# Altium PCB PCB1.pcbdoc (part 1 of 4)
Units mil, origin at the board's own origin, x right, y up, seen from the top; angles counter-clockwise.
Board outline 2559.1 x 3937 mil, 4 copper layers (Top Layer, Inner1, Inner2, Bottom Layer), stack 102.8 mil thick; 377 components, 358 nets, 1639 pads, 361 vias.
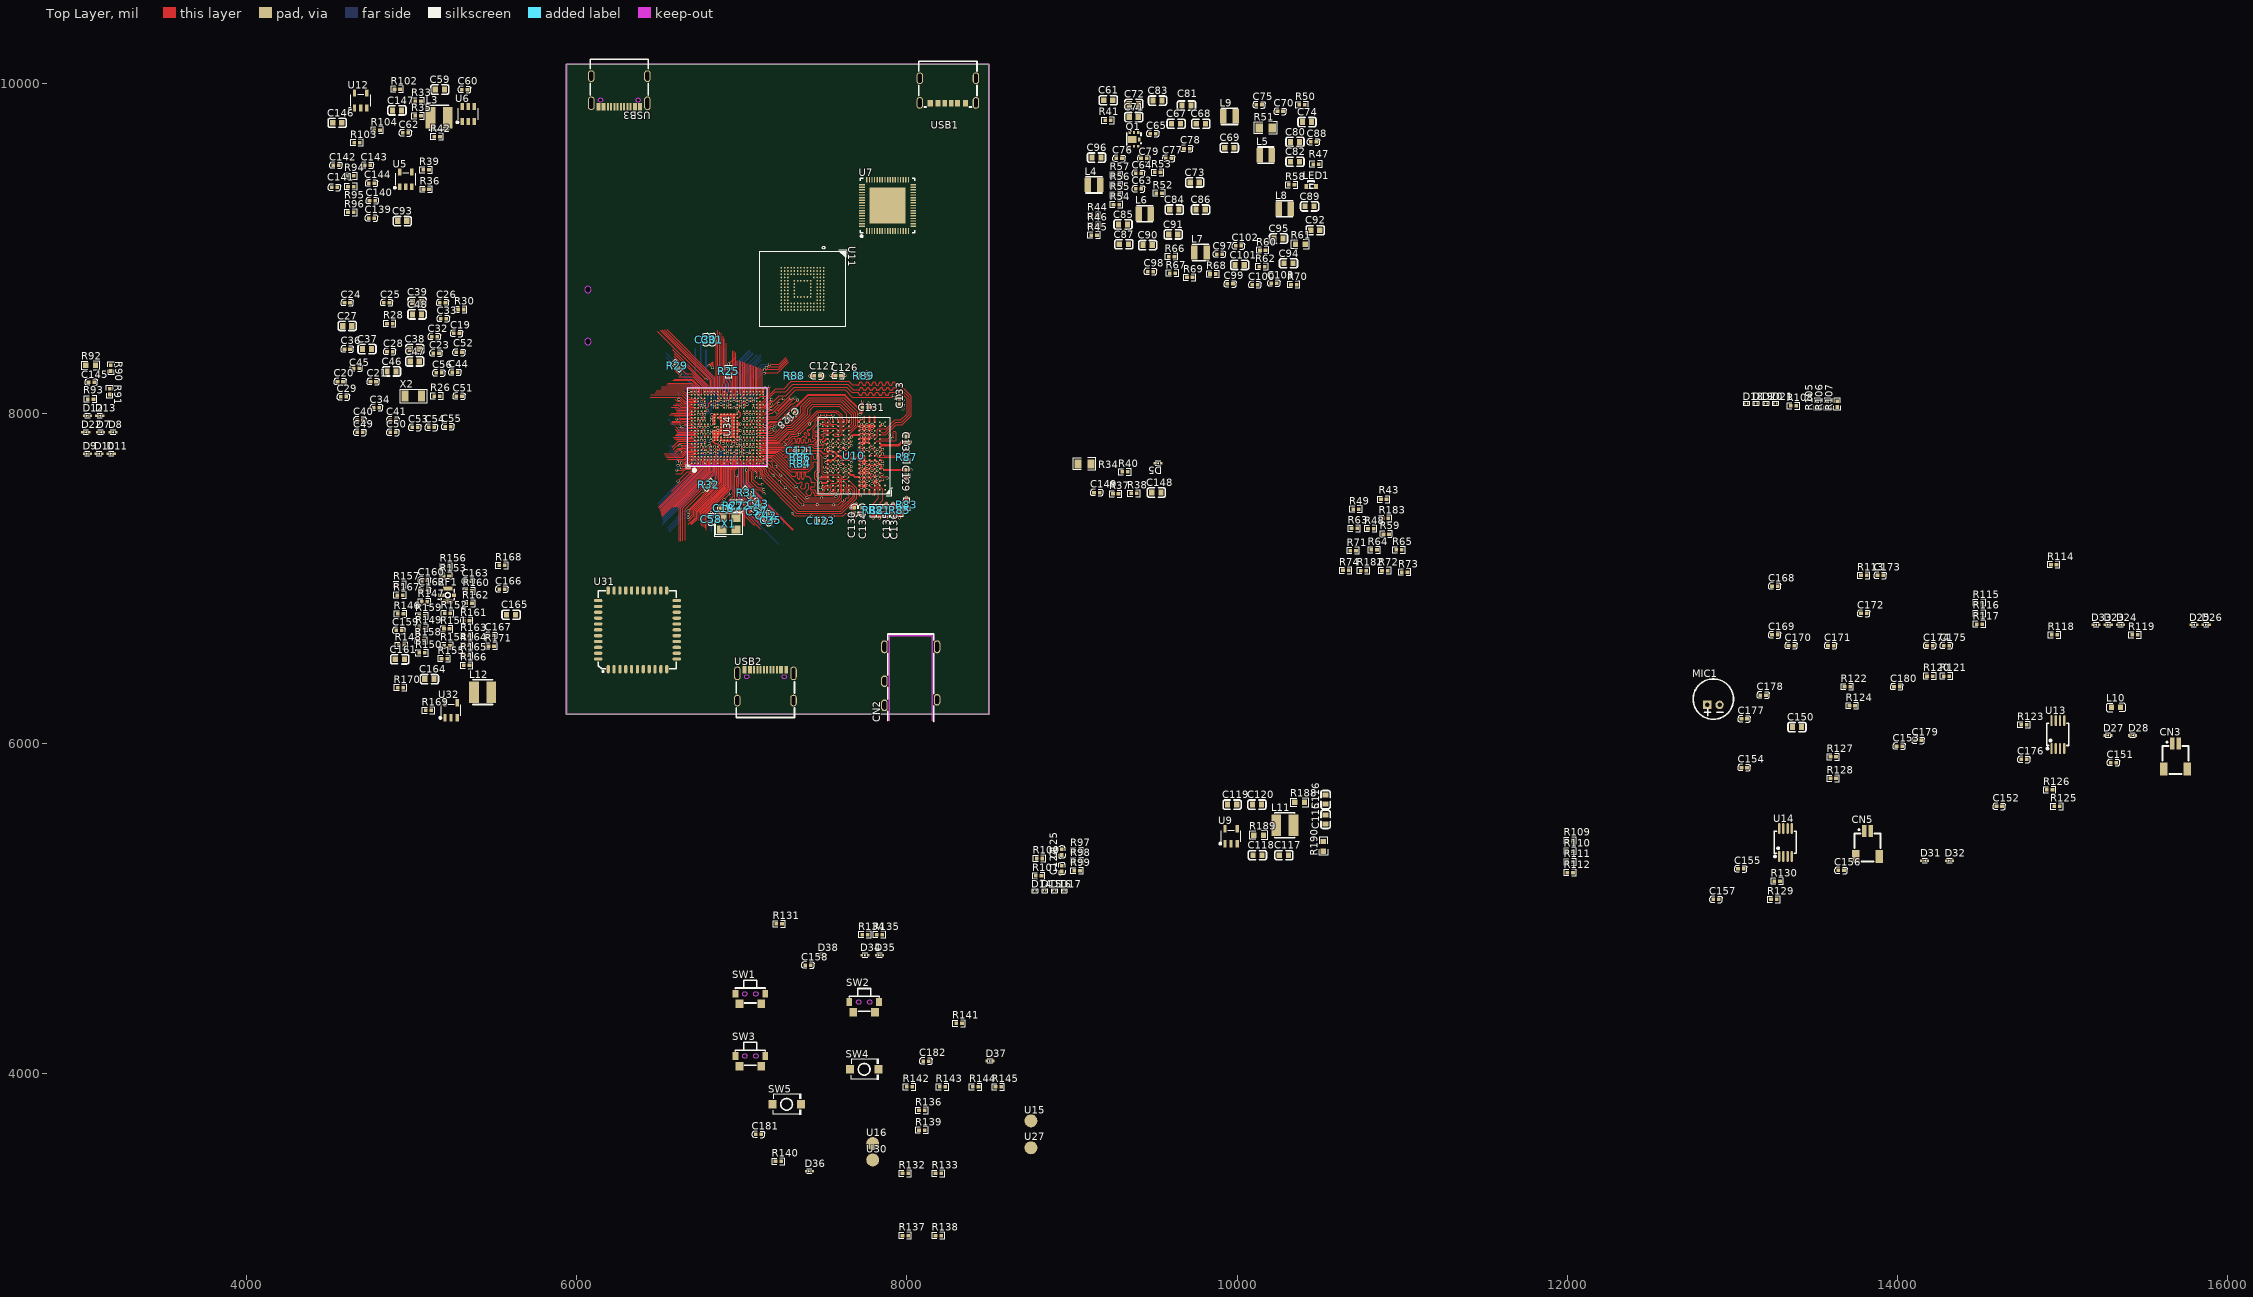
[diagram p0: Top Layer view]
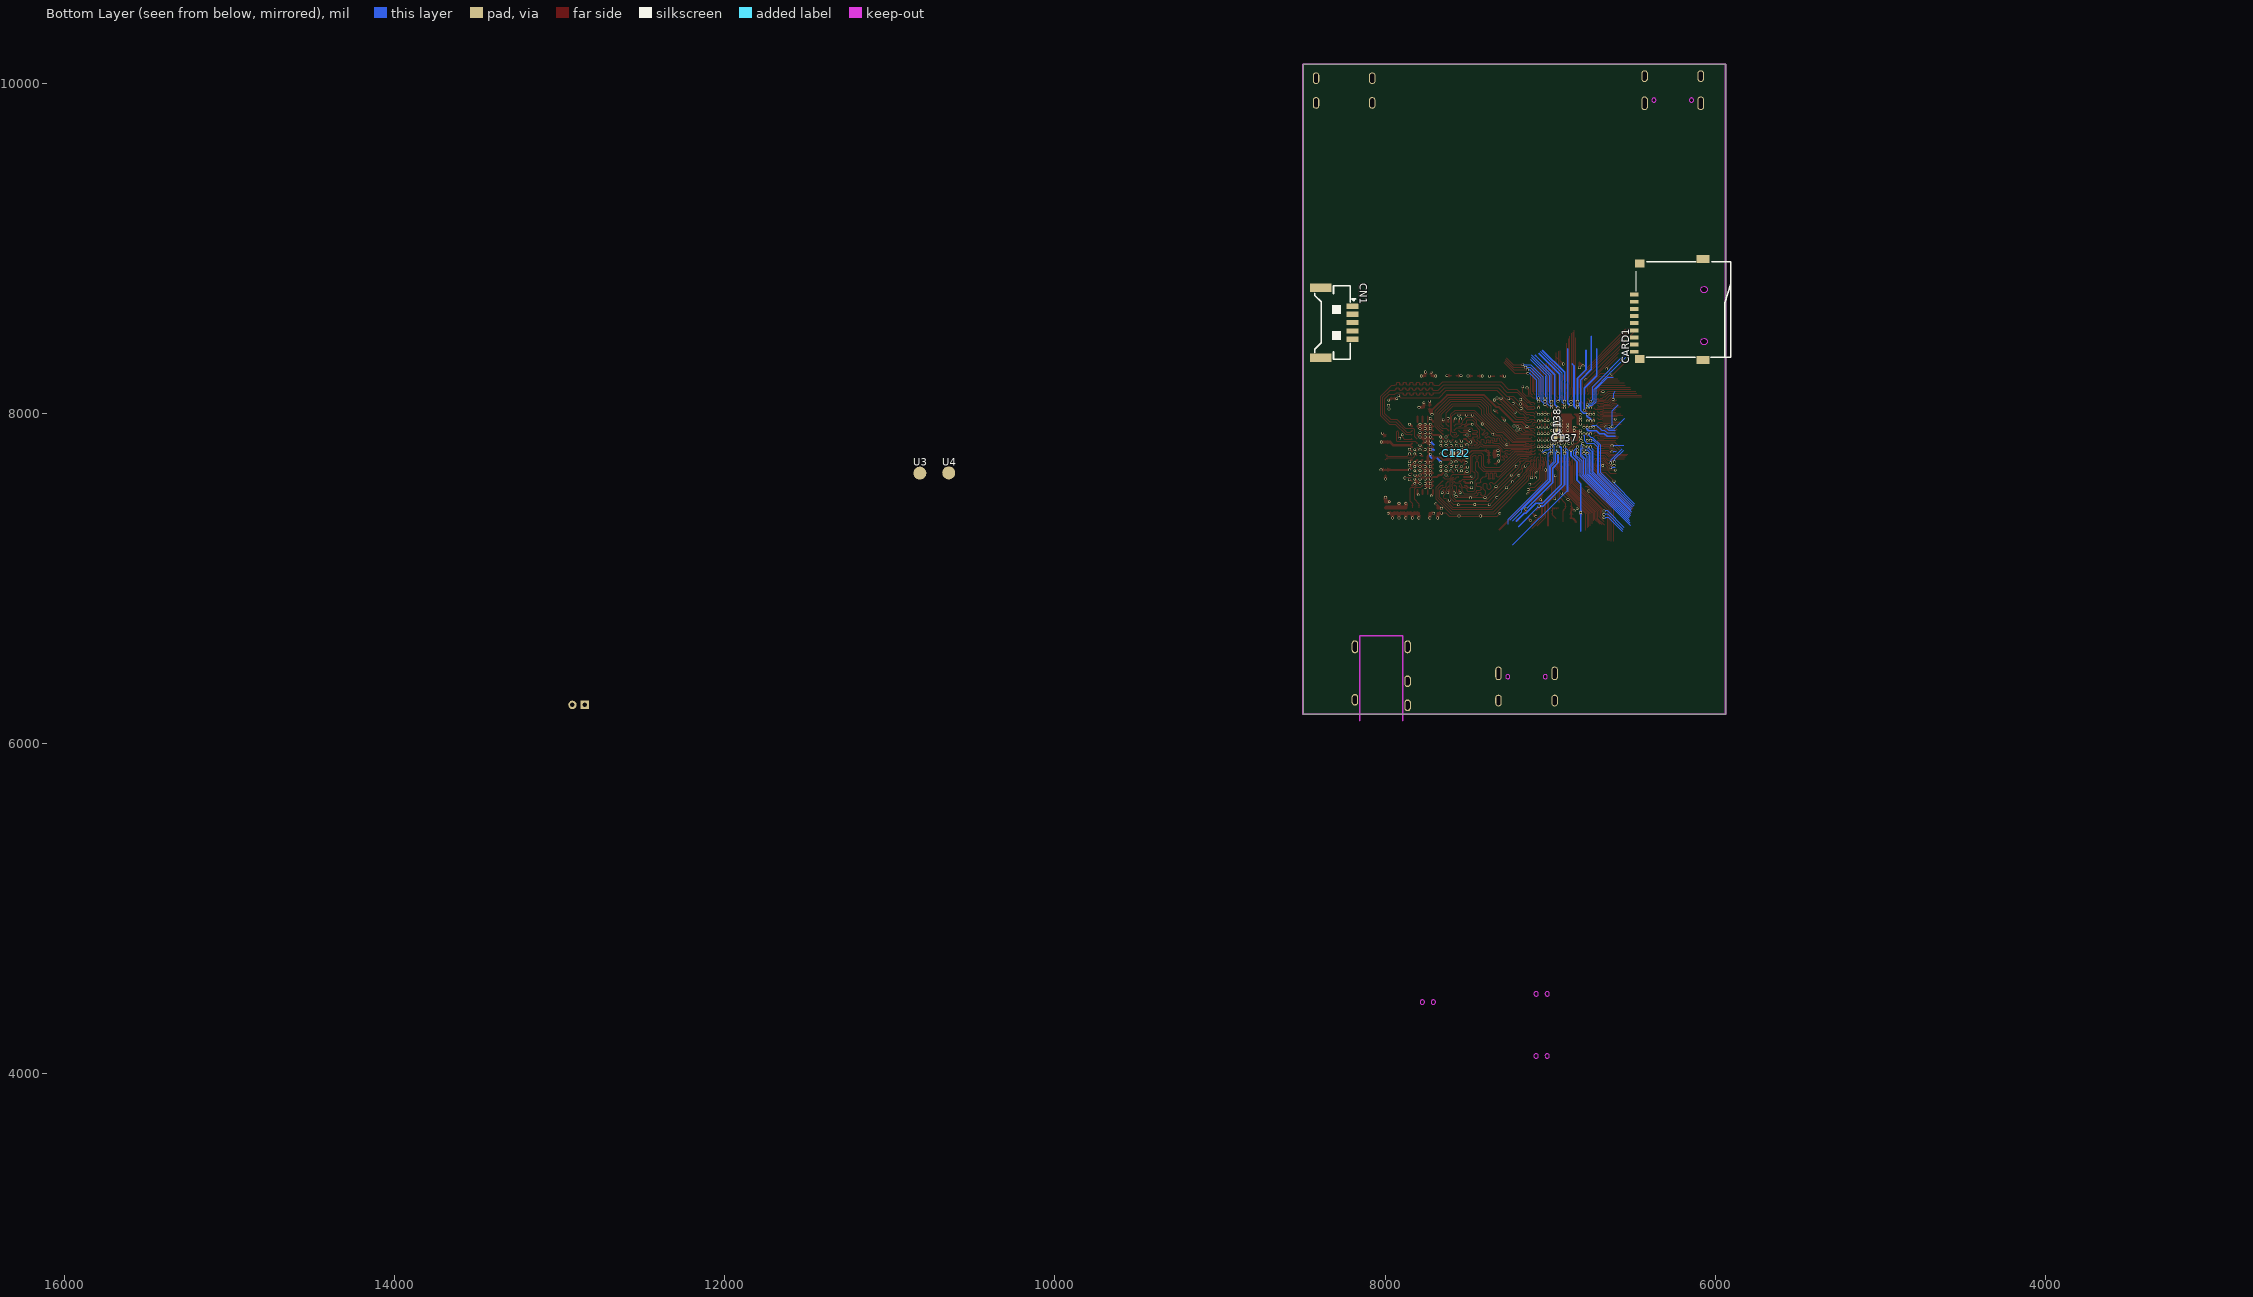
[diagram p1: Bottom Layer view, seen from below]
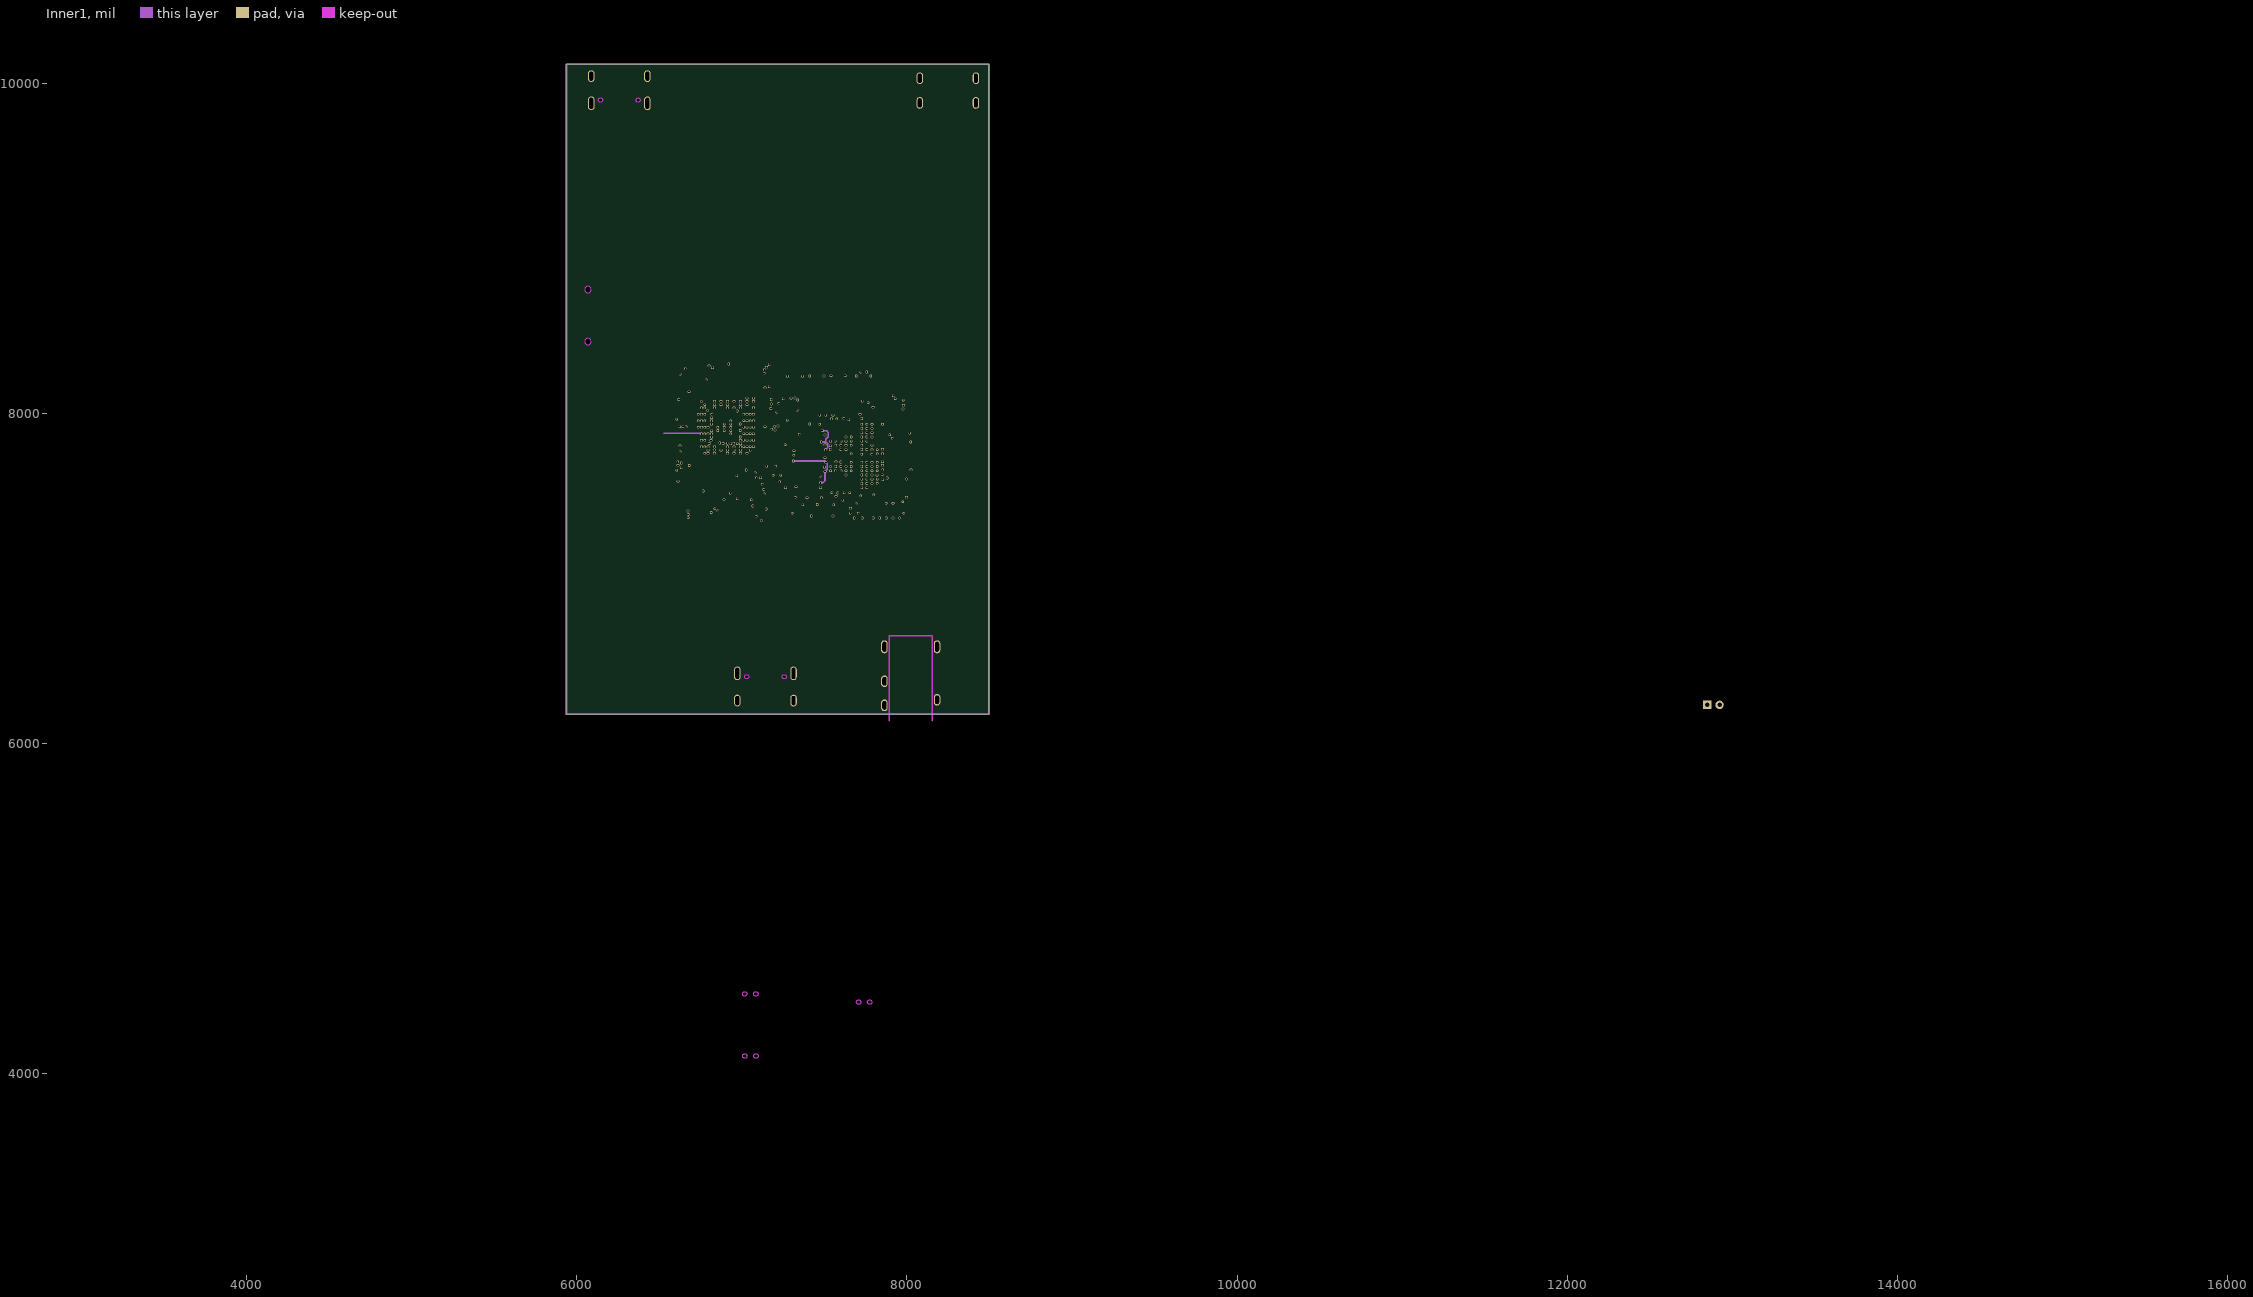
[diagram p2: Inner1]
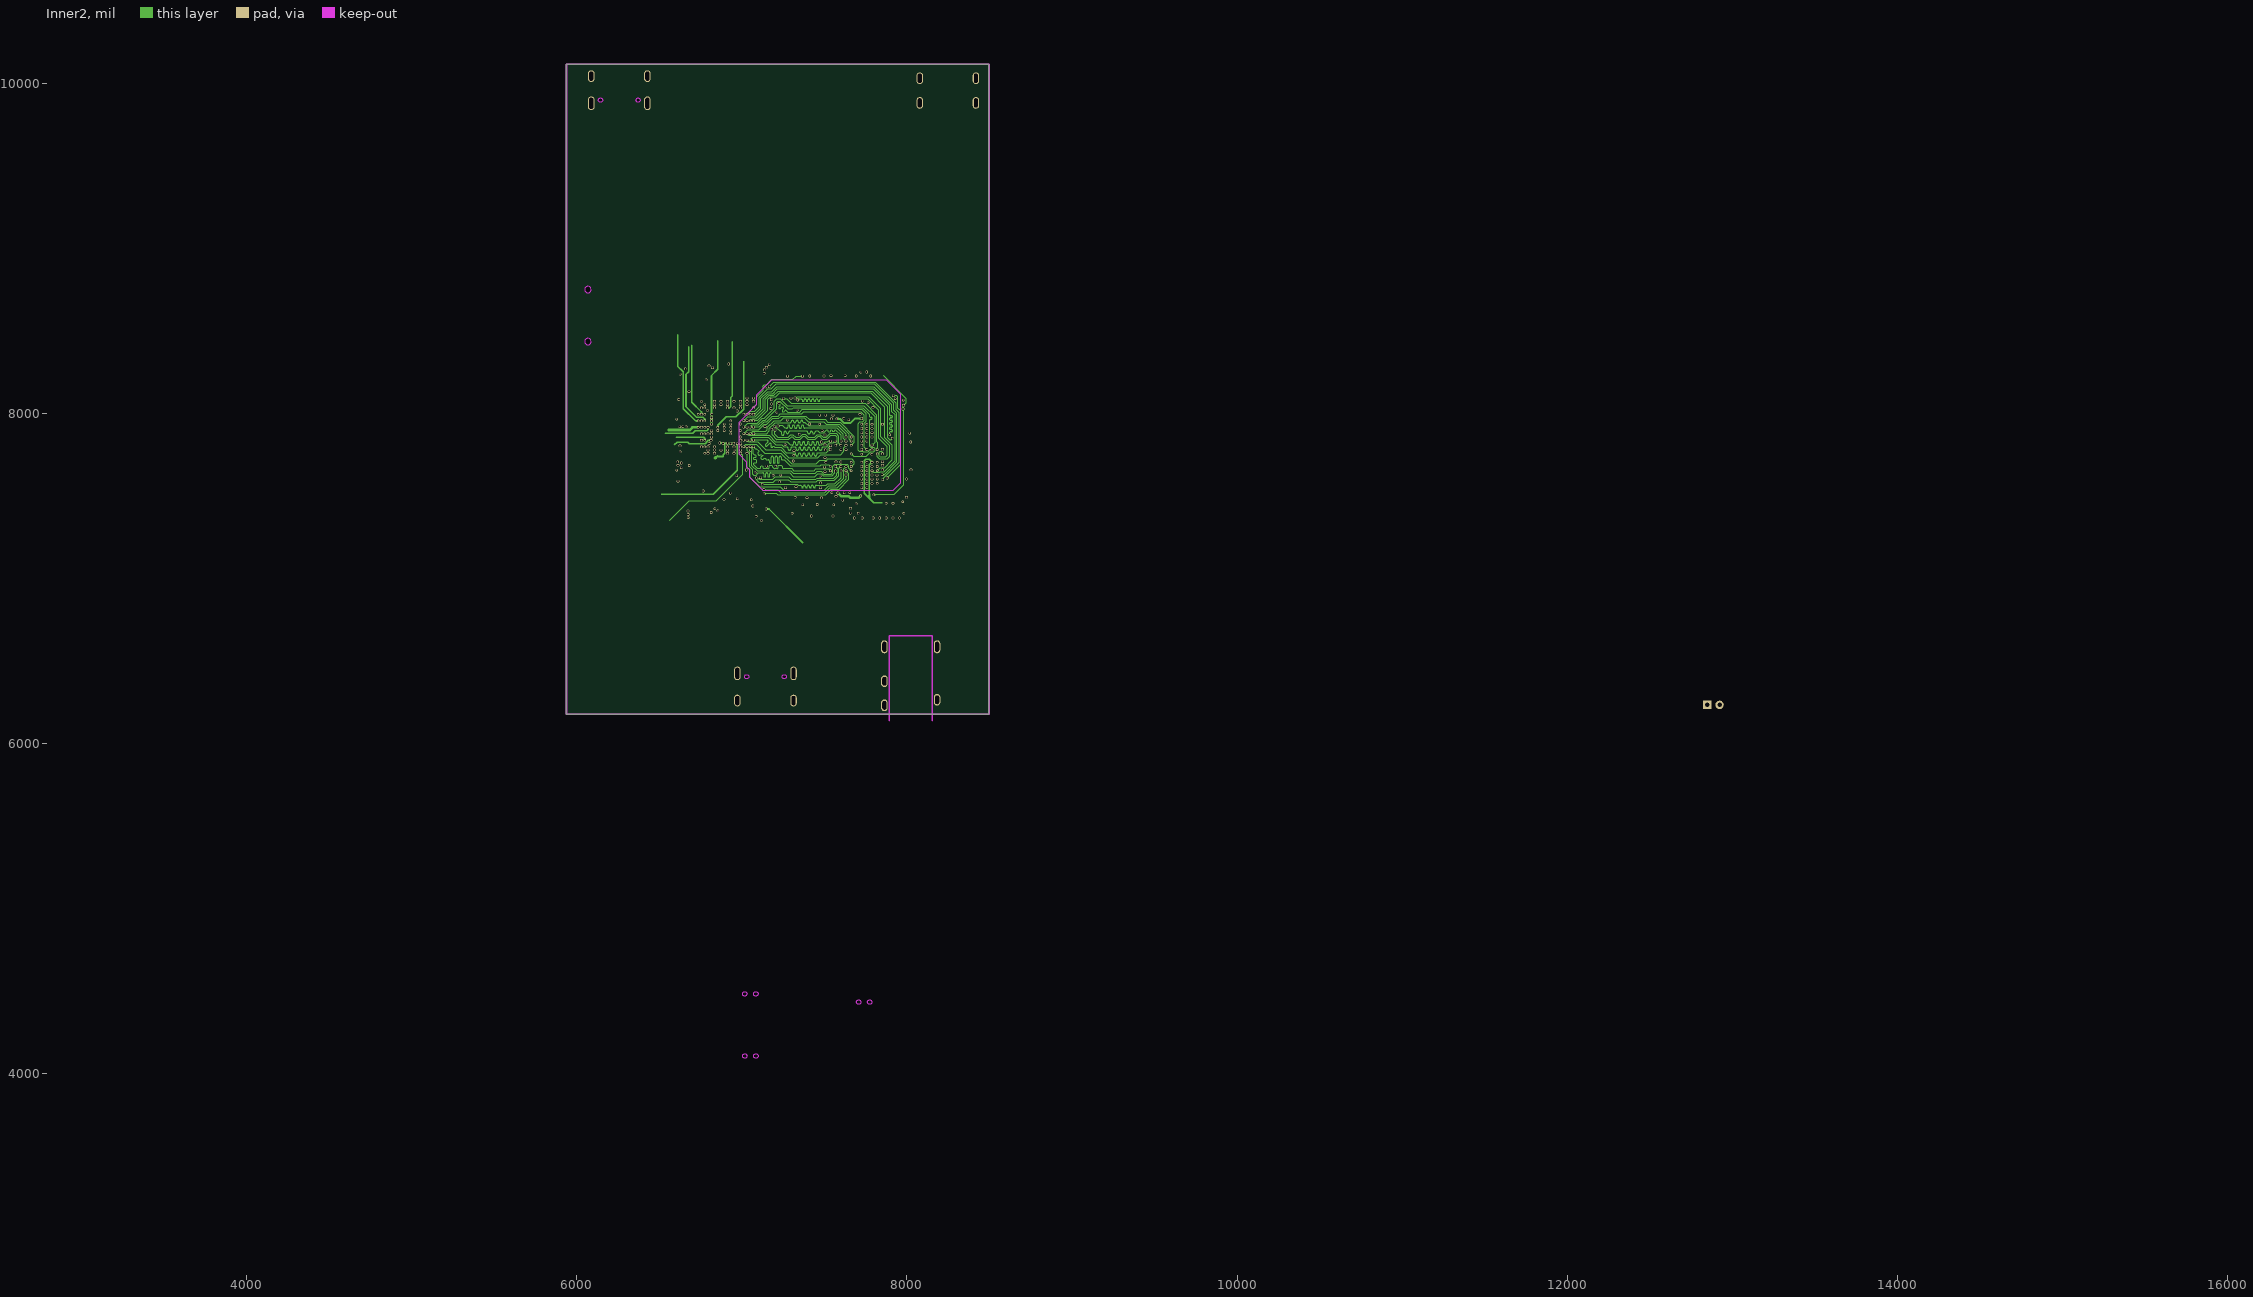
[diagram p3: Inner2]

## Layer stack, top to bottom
Top Solder Mask Layer: solder mask 0.4, Dk 3.3
Top Layer: signal copper 1.4
Dielectric1: surface 59.4, FR4, Dk 4.5
Inner1: signal copper 1.4
Dielectric2: surface 18.9, PP, Dk 4.5
Inner2: signal copper 1.4
Dielectric3: surface 18.9, PP, Dk 4.5
Bottom Layer: signal copper 1.4
Bottom Solder Mask Layer: solder mask 0.4, Dk 3.3

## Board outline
5938.8,10113.3 5938.8,6176.3 8497.9,6176.3 8497.9,10113.3

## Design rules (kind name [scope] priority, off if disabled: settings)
BoardOutlineClearance copperThickness1oz [All] p0: genericclearance=10 ignorepadtopadclearanceinfootprint=FALSE except(0: Arc-SplitContinuation Track-SplitContinuation SMDPad-SplitContinuation THPad-SplitContinuation Via-SplitContinuation Fill-SplitContinuation Poly-SplitContinuation Region-SplitContinuation Text-SplitContinuation)
BoardOutlineClearance copperThickness2oz [All] p0: genericclearance=10 ignorepadtopadclearanceinfootprint=FALSE except(0: Arc-SplitContinuation Track-SplitContinuation SMDPad-SplitContinuation THPad-SplitContinuation Via-SplitContinuation Fill-SplitContinuation Poly-SplitContinuation Region-SplitContinuation Text-SplitContinuation)
BoardOutlineClearance Plane_innerPlane [All] p0: genericclearance=10 ignorepadtopadclearanceinfootprint=FALSE except(0: Arc-SplitContinuation Track-SplitContinuation SMDPad-SplitContinuation THPad-SplitContinuation Via-SplitContinuation Fill-SplitContinuation Poly-SplitContinuation Region-SplitContinuation Text-SplitContinuation)
BoardOutlineClearance Copper_copperRegion [All] p0: genericclearance=10 ignorepadtopadclearanceinfootprint=FALSE except(0: Arc-SplitContinuation Track-SplitContinuation SMDPad-SplitContinuation THPad-SplitContinuation Via-SplitContinuation Fill-SplitContinuation Poly-SplitContinuation Region-SplitContinuation Text-SplitContinuation)
BoardOutlineClearance otherClearance [All] p0: genericclearance=10 ignorepadtopadclearanceinfootprint=FALSE except(0: Arc-SplitContinuation Track-SplitContinuation SMDPad-SplitContinuation THPad-SplitContinuation Via-SplitContinuation Fill-SplitContinuation Poly-SplitContinuation Region-SplitContinuation Text-SplitContinuation)
Clearance copperThickness1oz [All] p1: gap=7 ignorepadtopadclearanceinfootprint=FALSE
Clearance copperThickness2oz [All] p1: gap=7 ignorepadtopadclearanceinfootprint=FALSE
Clearance Plane_innerPlane [All] p1: gap=7 ignorepadtopadclearanceinfootprint=FALSE
Clearance Copper_copperRegion [All] p1: gap=7 ignorepadtopadclearanceinfootprint=FALSE
Clearance otherClearance [All] p1: gap=7 ignorepadtopadclearanceinfootprint=FALSE
DiffPairsRouting differentialPair [All] p1: maxuncoupledlength=10 minlimit=6 maxlimit=Infinity mostfreqgap=6 toplayer_minwidth=5 toplayer_prefwidth=10 toplayer_maxwidth=100 bottomlayer_minwidth=5 bottomlayer_prefwidth=10 bottomlayer_maxwidth=100 midlayer1_minwidth=5 midlayer1_prefwidth=10 midlayer1_maxwidth=100 midlayer2_minwidth=5 midlayer2_prefwidth=10 midlayer2_maxwidth=100
PasteMaskExpansion pasteMaskExpansion [All] p1: expansion=0
PlaneConnect innerPlane [All] p1: planeconnectstyle=Relief reliefexpansion=20 reliefentries=4 reliefconductorwidth=10 reliefairgap=10
PolygonConnect copperRegion [All] p1: connectstyle=Relief reliefentries=4 reliefconductorwidth=10 polygonreliefangle="90 Angle" airgapwidth=10
RoutingVias viaSize [All] p1: viastyle="Through Hole" holewidth=8 minholewidth=8 maxholewidth=248.0314 width=8 minwidth=8 maxwidth=248.0314
SolderMaskExpansion solderMaskExpansion [IsVia] p1: useseparateexpansions=TRUE expansion=-1000 expansionbottom=-1000
SolderMaskExpansion solderMaskExpansion [All] p2: useseparateexpansions=TRUE expansion=2 expansionbottom=2
Width copperThickness1oz [All] p1: maxlimit=100 minlimit=4 preferedwidth=4
Width copperThickness2oz [All] p1: maxlimit=100 minlimit=8 preferedwidth=10

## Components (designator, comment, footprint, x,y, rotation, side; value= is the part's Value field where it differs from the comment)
C18 "18pF" C0402#1 6891.3,7423.5 r0 top
C19 "22pF" C0402#2 5273.8,8483.3 r0 top
C20 "1nF" C0402#2 4568.6,8191.9 r0 top
C21 "1nF" C0402#3 4768.7,8191.9 r0 top
C22 "18pF" C0402#2 6988.8,7439.9 r270 top
C23 "22pF" C0402#2 5149.2,8364.2 r0 top
C24 "2.2uF" C0402#3 4611,8669.3 r0 top
C25 "470nF" C0402#1 4850.2,8669.3 r0 top
C26 "470nF" C0402#2 5189.3,8669.3 r0 top
C27 "10uF" C0603#1 4611,8529.1 r0 top
C28 "2.2uF" C0402#2 4868.8,8373.3 r0 top
C29 "2.2uF" C0402#3 4588.5,8099.1 r0 top
C30 "100nF" C0402#3 6783.7,8446.6 r270 top
C31 "100nF" C0402#2 6823.2,8446.6 r270 top
C32 "100nF" C0402#2 5139.3,8464.2 r0 top
C33 "100nF" C0402#2 5193.8,8573.3 r0 top
C34 "100nF" C0402#1 4788.6,8034.2 r0 top
C35 "100nF" C0402#4 7176.2,7350.7 r225 top
C36 "100nF" C0402#3 4611,8389 r0 top
C37 "10uF" C0603#2 4730.6,8389 r0 top
C38 "10uF" C0603#3 5019.7,8389 r0 top
C39 "10uF" C0603#3 5033.9,8674 r0 top
C40 "2.2uF" C0402#2 4688.5,7959 r0 top
C41 "2.2uF" C0402#3 4888.6,7959 r0 top
C42 "100nF" C0402#5 7148.8,7378.9 r225 top
C43 "220nF" C0402#2 7101.6,7451.2 r135 top
C44 "100nF" C0402#2 5263.8,8248.3 r0 top
C45 "100nF" C0402#3 4666,8273.7 r0 top
C46 "10uF" C0603#3 4878.8,8253.3 r0 top
C47 "10uF" C0603#3 5019.7,8313.7 r0 top
C48 "10uF" C0603#3 5033.9,8598.7 r0 top
C49 "2.2uF" C0402#2 4688.5,7883.7 r0 top
C50 "2.2uF" C0402#3 4888.6,7883.7 r0 top
C51 "100nF" C0402#2 5288.8,8103.3 r0 top
C52 "1uF" C0402#2 5288.7,8368.7 r0 top
C53 "100nF" C0402#2 5021.2,7913.8 r0 top
C54 "100nF" C0402#1 5121.3,7913.8 r0 top
C55 "100nF" C0402#1 5221.4,7918.8 r0 top
C56 "100nF" C0402#1 5166.4,8243.8 r0 top
C57 "100nF" C0402#1 7092.6,7403.9 r315 top
C58 "100nF" C0402#2 6815.6,7358 r270 top
C59 "10uF" C0603#2 5171.9,9960.6 r0 top
C60 "1uF" C0402#1 5321.9,9960.6 r0 top
C61 "10uF" C0603#3 9220.3,9895.6 r0 top
C62 "100nF" C0402#2 4963.8,9698.3 r0 top
C63 "4.7uF" C0402#2 9403.8,9358.3 r0 top
C64 "4.7uF" C0402#2 9403.8,9453.3 r0 top
C65 "4.7uF" C0402#2 9491,9693.3 r0 top
C67 "10uF" C0603#3 9631,9753.3 r0 top
C68 "10uF" C0603#3 9781,9753.3 r0 top
C69 "10uF" C0603#3 9953.8,9608.3 r0 top
C70 "4.7uF" C0402#3 10262,9828.3 r0 top
C71 "10uF" C0603#3 9374.4,9793.3 r0 top
C72 "10uF" C0603#3 9375.3,9873.3 r0 top
C73 "10uF" C0603#3 9743.8,9398.3 r0 top
C74 "10uF" C0603#3 10423.8,9763.3 r0 top
C75 "1uF" C0402#2 10134.4,9868.3 r0 top
C76 "4.7uF" C0402#2 9286,9543.3 r0 top
C77 "4.7uF" C0402#2 9586,9543.3 r0 top
C78 "4.7uF" C0402#2 9696,9603.3 r0 top
C79 "4.7uF" C0402#2 9436,9543.3 r0 top
C80 "10uF" C0603#3 10351.1,9643.3 r0 top
C81 "10uF" C0603#3 9693.8,9863.3 r0 top
C82 "10uF" C0603#3 10351.1,9523.3 r0 top
C83 "10uF" C0603#3 9518.8,9893.3 r0 top
C84 "10uF" C0603#3 9620.4,9233.3 r0 top
C85 "10uF" C0603#3 9309.5,9143.3 r0 top
C86 "10uF" C0603#3 9779.5,9233.3 r0 top
C87 "10uF" C0603#3 9314.5,9023.3 r0 top
C88 "1uF" C0402#2 10463.8,9643.3 r0 top
C89 "10uF" C0603#3 10439.4,9253.3 r0 top
C90 "22uF" C0603#3 9458.8,9018.3 r0 top
C91 "22uF" C0603#3 9613.8,9083.3 r0 top
C92 "22uF" C0603#3 10473.8,9108.3 r0 top
C93 "10uF" C0603#3 4944.4,9163.3 r0 top
C94 "10uF" C0603#1 10312,8908.3 r0 top
C95 "10uF" C0603#3 10251.1,9058.3 r0 top
C96 "22uF" C0603#3 9148.8,9548.3 r0 top
C97 "4.7uF" C0402#2 9893.8,8963.3 r0 top
C98 "4.7uF" C0402#2 9476,8858.3 r0 top
C99 "4.7uF" C0402#2 9958.8,8783.3 r0 top
C100 "4.7uF" C0402#2 10108.8,8778.3 r0 top
C101 "10uF" C0603#3 10016,8898.3 r0 top
C102 "1uF" C0402#2 10008.8,9013.3 r0 top
C103 "4.7uF" C0402#2 10223.8,8788.3 r0 top
C115 "100nF" C0603#3 10536.3,5540 r90 top
C116 "100nF" C0603#3 10536.3,5660 r90 top
C117 "100nF" C0603#3 10283.8,5323.3 r0 top
C118 "100nF" C0603#3 10123.8,5323.3 r0 top
C119 "100nF" C0603#2 9970.7,5629.7 r0 top
C120 "100nF" C0603#2 10120.7,5629.7 r0 top
C121 "100nF" C0402#2 7355.6,7773.3 r0 top
C122 "1uF" C0402#2 7570.1,7757.8 r0 bottom
C123 "1uF" C0402#1 7479.1,7347.9 r180 top
C124 "1uF" C0402#1 8938.7,5241.9 r90 top
C125 "100nF" C0402#3 8938.7,5341.9 r90 top
C126 "1uF" C0402#1 7584.9,8227.3 r0 top
C127 "100nF" C0402#1 7456.8,8225.8 r180 top
C128 "1uF" C0402#1 7306.5,7989.4 r225 top
C129 "1uF" C0402#3 7998.3,7641.5 r270 top
C130 "100nF" C0402#1 7682.3,7411.3 r90 top
C131 "100nF" C0402#2 7746.9,8036.3 r0 top
C132 "100nF" C0402#2 7998.3,7842.6 r270 top
C133 "1uF" C0402#1 7953.5,8071.3 r90 top
C134 "100nF" C0402#1 7729.6,7411.3 r90 top
C135 "100nF" C0402#1 7874.9,7411.3 r90 top
C136 "100nF" C0402#1 7916.9,7411.3 r90 top
C137 "1uF" C0402#1 6951.4,7852.4 r180 bottom
C138 "100nF" C0402#2 6962.1,7912.6 r90 bottom
C139 "1uF" C0402#2 4758.3,9182.1 r0 top
C140 "100nF" C0402#2 4763.3,9287 r0 top
C141 "1uF" C0402#2 4533.8,9368.3 r0 top
C142 "100nF" C0402#1 4543.3,9501.9 r0 top
C143 "1uF" C0402#2 4733.3,9501.9 r0 top
C144 "100nF" C0402#2 4758.8,9393.3 r0 top
C145 "4.7uF" C0402#1 3061,8188.8 r0 top
C146 "10uF" C0603#2 4550.6,9759.2 r0 top
C147 "10uF" C0603#3 4912.1,9834.2 r0 top
C148 "10uF" C0603#3 9511.4,7519.8 r0 top
C149 "100nF" C0402#2 9151.4,7519.8 r0 top
C150 "10uF" C0603#2 13391.7,6098.8 r0 top
C151 "1uF" C0402#2 15308.8,5883.7 r0 top
C152 "100nF" C0402#1 14616.6,5618.8 r0 top
C153 "100nF" C0402#2 14011.4,5983.9 r0 top
C154 "33pF" C0402#2 13072,5854.1 r0 top
C155 "220nF" C0402#1 13051.6,5240.4 r0 top
C156 "1uF" C0402#3 13658.8,5230.8 r0 top
C157 "100nF" C0402#2 12901.5,5055.9 r0 top
C158 "1nF" C0402#1 7402.1,4657.7 r0 top
C159 "33pF" C0402#1 4924.3,6684.6 r0 top
C160 "33pF" C0402#1 5079.3,6989.6 r0 top
C161 "10uF" C0603#4 4929.6,6509.6 r0 top
C162 "4.7uF" C0402#1 5080.9,6928.2 r0 top
C163 "4.7uF" C0402#2 5345.9,6983.3 r0 top
C164 "10uF" C0603#5 5108.7,6389.6 r0 top
C165 "10uF" C0603#5 5603.5,6779.6 r0 top
C166 "100nF" C0402#1 5548.1,6934.6 r0 top
C167 "22pF" C0402#1 5483.3,6654.3 r0 top
C168 "100nF" C0402#1 13257.1,6952.6 r0 top
C169 "100nF" C0402#1 13257.1,6657.8 r0 top
C170 "33pF" C0402#1 13357.1,6592.9 r0 top
C171 "33pF" C0402#1 13596.3,6592.9 r0 top
C172 "33pF" C0402#2 13796.3,6787.7 r0 top
C173 "2.2uF" C0402#1 13896.4,7017.5 r0 top
C174 "100nF" C0402#1 14196.5,6592.9 r0 top
C175 "100nF" C0402#3 14296.5,6592.9 r0 top
C176 "220nF" C0402#3 14766.6,5903.3 r0 top
C177 "100pF" C0402#2 13072,6148.8 r0 top
C178 "33pF" C0402#2 13187,6293.3 r0 top
C179 "100nF" C0402#2 14126.4,6018.3 r0 top
C180 "1uF" C0402#3 13996.4,6343.4 r0 top
C181 "1nF" C0402#3 7102.1,3632.8 r0 top
C182 "100nF" C0402#2 8116.8,4076.7 r0 top
CARD1 "TF-01A" TF-SMD_TF-01A 6283.8,8628.3 r90 bottom
CN1 "1.25K-CB-5PWB" CONN-SMD_5P-P1.25_L5.5-W11.4-5PWB 8293.8,8548.3 r270 bottom
CN2 "ST-0277D00-052-142" AUDIO-TH_ST-0277D00-052-142 8023.8,6408.3 r90 top
CN3 "1.0-2PWB" CONN-SMD_2P-P1.00_DEALON_1.0-2PWB 15683.8,5923.3 r0 top
CN5 "1.0-2PWB" CONN-SMD_2P-P1.00_DEALON_1.0-2PWB 13818.8,5393.3 r0 top
D5 "ESD9B5V" SOD-923_L0.8-W0.6-LS1.0-BI-1#1 9521,7698.3 r180 top
D7 "ESD9B5V" SOD-923_L0.8-W0.6-LS1.0-BI-1#2 3117.4,7885.6 r0 top
D8 "ESD9B5V" SOD-923_L0.8-W0.6-LS1.0-BI-1#1 3192.2,7885.6 r0 top
D9 "ESD9B5V" SOD-923_L0.8-W0.6-LS1.0-BI-1#1 3037,7755.6 r0 top
D10 "ESD9B5V" SOD-923_L0.8-W0.6-LS1.0-BI-1#1 3107,7755.6 r0 top
D11 "ESD9B5V" SOD-923_L0.8-W0.6-LS1.0-BI-1#1 3181.8,7755.6 r0 top
D12 "ESD9B5V" SOD-923_L0.8-W0.6-LS1.0-BI-1#3 3037.1,7985.6 r0 top
D13 "ESD9B5V" SOD-923_L0.8-W0.6-LS1.0-BI-1#3 3111.9,7985.6 r0 top
D14 "ESD5451XZ-2/TR" X3-DFN0603-2_L0.6-W0.3-BI#1 8774.9,5109 r0 top
D15 "ESD5451XZ-2/TR" X3-DFN0603-2_L0.6-W0.3-BI#2 8834,5109 r0 top
D16 "ESD5451XZ-2/TR" X3-DFN0603-2_L0.6-W0.3-BI#3 8893.1,5109 r0 top
D17 "ESD5451XZ-2/TR" X3-DFN0603-2_L0.6-W0.3-BI#2 8952.1,5109 r0 top
D18 "ESD5451XZ-2/TR" X3-DFN0603-2_L0.6-W0.3-BI#1 13083.5,8059.4 r0 top
D19 "ESD5451XZ-2/TR" X3-DFN0603-2_L0.6-W0.3-BI#3 13142.6,8059.4 r0 top
D20 "ESD5451XZ-2/TR" X3-DFN0603-2_L0.6-W0.3-BI#1 13201.6,8059.4 r0 top
D21 "ESD5451XZ-2/TR" X3-DFN0603-2_L0.6-W0.3-BI#3 13260.7,8059.4 r0 top
D22 "ESD9B5V" SOD-923_L0.8-W0.6-LS1.0-BI-1#2 3027.6,7885.6 r0 top
D23 "ESD9B5V" SOD-923_L0.8-W0.6-LS1.0-BI-1#1 15276.6,6718.1 r0 top
D24 "ESD9B5V" SOD-923_L0.8-W0.6-LS1.0-BI-1#1 15351.4,6718.1 r0 top
D25 "ESD9B5V" SOD-923_L0.8-W0.6-LS1.0-BI-1#1 15795.2,6718.1 r0 top
D26 "ESD9B5V" SOD-923_L0.8-W0.6-LS1.0-BI-1#1 15870,6718.1 r0 top
D27 "ESD9B5V" SOD-923_L0.8-W0.6-LS1.0-BI-1#1 15274.6,6048.5 r0 top
D28 "ESD9B5V" SOD-923_L0.8-W0.6-LS1.0-BI-1#1 15424.2,6048.5 r0 top
D31 "ESD9B5V" SOD-923_L0.8-W0.6-LS1.0-BI-1#1 14164.8,5290.6 r0 top
D32 "ESD9B5V" SOD-923_L0.8-W0.6-LS1.0-BI-1#1 14314.4,5290.6 r0 top
D33 "ESD9B5V" SOD-923_L0.8-W0.6-LS1.0-BI-1#1 15201.8,6718.1 r0 top
D34 "ESD9B5V" SOD-923_L0.8-W0.6-LS1.0-BI-1#2 7747,4717.6 r0 top
D35 "ESD9B5V" SOD-923_L0.8-W0.6-LS1.0-BI-1#1 7834.4,4717.6 r0 top
D36 "ESD9B5V" SOD-923_L0.8-W0.6-LS1.0-BI-1#3 7409.6,3409.6 r0 top
D37 "ESD9B5V" SOD-923_L0.8-W0.6-LS1.0-BI-1#2 8504.4,4076.7 r0 top
D38 "ESD9B5V" SOD-923_L0.8-W0.6-LS1.0-BI-1#1 7489.5,4717.6 r0 top
L3 "2.2uH" IND-SMD_L3.0-W3.0#1 5166.9,9790.6 r0 top
L4 "1uH" IND-SMD_L2.5-W2.0_MHCH252012A 9133.8,9383.3 r0 top
L5 "1uH" IND-SMD_L2.5-W2.0_MHCH252012A 10173.8,9563.3 r0 top
L6 "1uH" IND-SMD_L2.5-W2.0_MHCH252012A 9441,9208.3 r0 top
L7 "1uH" IND-SMD_L2.5-W2.0_MHCH252012A 9778.8,8973.3 r0 top
L8 "1uH" IND-SMD_L2.5-W2.0_MHCH252012A 10288.8,9238.3 r0 top
L9 "1uH" IND-SMD_L2.5-W2.0_MHCH252012A 9953.8,9798.3 r0 top
L10 "CBG160808U601T" L0603 15323.8,6218.3 r0 top
L11 "2.2uH" IND-SMD_L3.0-W3.0#2 10289.5,5504.7 r0 top
L12 "2.2uH" IND-SMD_L3.0-W3.0#1 5431.6,6310.9 r0 top
LED1 "XL-1606UGC" LED-SMD_L1.7-W1.1-R-RD_GREEN 10448.8,9373.3 r0 top
MIC1 "GMI6027P-2C30DB" MIC-TH_BD6.0-P1.90-D0.4-L 12885.1,6233.3 r0 top
Q1 "CJM1216" DFN-6L_L2.0-W2.0-P0.65-BL_CJM1216 9378.8,9658.3 r0 top
R25 "33Ω" R0402#1 6921.1,8253.4 r270 top
R26 "10MΩ" R0402#2 5154.2,8104.1 r0 top
R27 "0Ω" R0402#1 6948.9,7440.2 r270 top
R28 "0Ω" R0402#1 4868.8,8543.3 r0 top
R29 "33Ω" R0402#3 6609,8287.6 r315 top
R30 "33Ω" R0402#1 5298.8,8628.3 r0 top
R31 "0Ω" R0402#4 7034.5,7519.4 r135 top
R32 "33Ω" R0402#3 6800.4,7565.7 r45 top
R33 "10kΩ" R0402#1 5040.3,9890.9 r0 top
R34 "0Ω" R0805#1 9076,7693.3 r0 top
R35 "0Ω" R0402#1 5040.3,9800.9 r0 top
R36 "6.8kΩ" R0402#4 5089.5,9356.7 r0 top
R37 "5.1kΩ" R0402#1 9265.5,7511 r0 top
R38 "5.1kΩ" R0402#1 9376.4,7514.8 r0 top
R39 "100kΩ" R0402#1 5088.8,9473.3 r0 top
R40 "10kΩ" R0402#1 9321.4,7644.8 r0 top
R41 "68kΩ" R0402#1 9218.8,9773.3 r0 top
R42 "13kΩ" R0402#1 5155.3,9675.6 r0 top
R43 "0Ω" R0402#1 10888.8,7478.3 r0 top
R44 "0Ω" R0402#1 9134.5,9198.3 r0 top
R45 "0Ω" R0402#1 9134.5,9078.3 r0 top
R46 "0Ω" R0402#1 9134.5,9138.3 r0 top
R47 "0Ω" R0402#1 10478.8,9508.3 r0 top
R48 "0Ω" R0402#2 10810.5,7300.6 r0 top
R49 "0Ω" R0402#2 10720.5,7419.2 r0 top
R50 "10kΩ" R0402#1 10393.8,9868.3 r0 top
R51 "10mΩ" R0805#2 10173.8,9728.3 r0 top
R52 "0Ω" R0402#1 9528.8,9333.3 r0 top
R53 "0Ω" R0402#1 9519.5,9458.3 r0 top
R54 "0Ω" R0402#1 9269.5,9263.3 r0 top
R55 "0Ω" R0402#1 9269.5,9323.3 r0 top
R56 "0Ω" R0402#1 9269.5,9383.3 r0 top
R57 "0Ω" R0402#1 9269.5,9443.3 r0 top
R58 "10kΩ" R0402#1 10331.1,9383.3 r0 top
R59 "0Ω" R0402#1 10903.8,7268.3 r0 top
R60 "470Ω" R0402#1 10156,8988.3 r0 top
R61 "10mΩ" R0603#1 10383.8,9023.3 r0 top
R62 "470Ω" R0402#1 10151,8888.3 r0 top
R63 "0Ω" R0402#2 10710.5,7302.1 r0 top
R64 "0Ω" R0402#1 10830.5,7171.9 r0 top
R65 "0Ω" R0402#4 10980.6,7171.9 r0 top
R66 "0Ω" R0402#1 9603.8,8948.3 r0 top
R67 "0Ω" R0402#1 9609.5,8848.3 r0 top
R68 "0Ω" R0402#1 9853.8,8843.3 r0 top
R69 "0Ω" R0402#1 9713.8,8823.3 r0 top
R70 "0Ω" R0402#1 10343.8,8778.3 r0 top
R71 "0Ω" R0402#1 10703.8,7168.3 r0 top
R72 "0Ω" R0402#4 10895.6,7047.3 r0 top
R73 "0Ω" R0402#4 11015.6,7037.4 r0 top
R74 "0Ω" R0402#1 10658.8,7048.3 r0 top
R81 "240Ω" R0402#1 7835.4,7411.3 r270 top
R82 "240Ω" R0402#1 7796,7411.3 r270 top
R83 "2kΩ" R0402#1 7998.3,7446.7 r90 top
R84 "2kΩ" R0402#4 7355.6,7693.3 r180 top
R85 "2kΩ" R0402#4 7955.9,7411.3 r90 top
R86 "2kΩ" R0402#1 7355.6,7733.3 r0 top
R87 "100Ω" R0402#4 7998.3,7734.7 r90 top
R88 "240Ω" R0402#4 7318.4,8225.8 r180 top
R89 "0Ω" R0402#1 7738.4,8225.8 r0 top
R90 "10kΩ" R0402#1 3178.8,8273.3 r270 top
R91 "47kΩ" R0402#1 3171.7,8131.1 r270 top
R92 "2.2Ω" R0603#1 3056.7,8290.4 r0 top
R93 "1kΩ" R0402#1 3056.7,8085.4 r0 top
R94 "10kΩ" R0402#4 4633.3,9437 r0 top
R95 "10kΩ" R0402#4 4633.3,9372 r0 top
R96 "10kΩ" R0402#4 4633.3,9217.1 r0 top
R97 "0Ω" R0402#4 9031.7,5349 r0 top
R98 "0Ω" R0402#4 9031.7,5289 r0 top
R99 "0Ω" R0402#4 9031.7,5229 r0 top
R100 "47kΩ" R0402#1 8803.8,5303.3 r0 top
R101 "0Ω" R0402#1 8798.8,5198.3 r0 top
R102 "0Ω" R0402#1 4913.8,9963.3 r0 top
R103 "6.8kΩ" R0402#1 4670.1,9639.2 r0 top
R104 "100kΩ" R0402#1 4792.5,9714.2 r0 top
R105 "0Ω" R0402#1 13515.2,8055.1 r90 top
R106 "0Ω" R0402#1 13575.2,8055.1 r90 top
R107 "1kΩ" R0402#1 13635.2,8055.1 r90 top
R108 "47kΩ" R0402#1 13370.2,8044.4 r0 top
R109 "0Ω" R0402#4 12017.8,5412.3 r0 top
R110 "0Ω" R0402#4 12017.8,5347.3 r0 top
R111 "0Ω" R0402#4 12017.8,5282.4 r0 top
R112 "0Ω" R0402#4 12017.8,5217.4 r0 top
R113 "2kΩ" R0402#1 13796.3,7017.5 r0 top
R114 "1MΩ" R0402#2 14946.7,7082.5 r0 top
R115 "0Ω" R0402#4 14496.6,6852.6 r0 top
R116 "47kΩ" R0402#4 14496.6,6787.7 r0 top
R117 "0Ω" R0402#4 14496.6,6722.8 r0 top
R118 "100kΩ" R0402#1 14951.7,6658.3 r0 top
R119 "0Ω" R0402#2 15438.8,6658.3 r0 top
R120 "22Ω" R0402#4 14196.5,6408.4 r0 top
R121 "22Ω" R0402#2 14296.5,6408.4 r0 top
R122 "1kΩ" R0402#4 13696.3,6343.4 r0 top
R123 "1MΩ" R0402#2 14766.6,6113.4 r0 top
R124 "1.5kΩ" R0402#4 13726.3,6228.4 r0 top
R125 "20kΩ" R0402#4 14966.7,5618.8 r0 top
R126 "100kΩ" R0402#4 14921.8,5718.8 r0 top
R127 "1.5kΩ" R0402#4 13611.3,5919 r0 top
R128 "1kΩ" R0402#4 13611.3,5789.1 r0 top
R129 "20kΩ" R0402#1 13251.6,5055.9 r0 top
R130 "100kΩ" R0402#4 13271.8,5165.9 r0 top
R131 "10kΩ" R0402#1 7227.2,4907.3 r0 top
R132 "10kΩ" R0402#1 7991.2,3396 r0 top
R133 "47kΩ" R0402#1 8191.3,3396 r0 top
R134 "5.6kΩ" R0402#4 7747,4842.3 r0 top
R135 "10kΩ" R0402#4 7834.4,4842.3 r0 top
R136 "10kΩ" R0402#4 8091.3,3777.4 r0 top
R137 "1kΩ" R0402#1 7991.2,3019.6 r0 top
R138 "1kΩ" R0402#1 8191.3,3019.6 r0 top
R139 "1kΩ" R0402#4 8091.3,3657.7 r0 top
R140 "1kΩ" R0402#2 7222.2,3469.5 r0 top
R141 "1kΩ" R0402#2 8316.9,4304.6 r0 top
R142 "10kΩ" R0402#2 8016.8,3920.6 r0 top
R143 "10kΩ" R0402#4 8216.9,3920.6 r0 top
R144 "10kΩ" R0402#1 8416.9,3920.6 r0 top
R145 "10kΩ" R0402#4 8554.4,3920.6 r0 top
R146 "0Ω" R0402#1 4934.2,6784.6 r0 top
R147 "0Ω" R0402#1 5078.8,6858.3 r0 top
R148 "0Ω" R0402#4 4939.2,6594.6 r0 top
R149 "10kΩ" R0402#4 5064.3,6698.2 r0 top
R150 "10kΩ" R0402#4 5064.3,6548.2 r0 top
R151 "33kΩ" R0402#1 5213.8,6693.3 r0 top
R152 "33kΩ" R0402#1 5218.8,6788.3 r0 top
R153 "33kΩ" R0402#4 5210.9,7013.2 r0 top
R154 "33kΩ" R0402#4 5215.9,6593.2 r0 top
R155 "33kΩ" R0402#1 5198.8,6513.3 r0 top
R156 "33kΩ" R0402#1 5210.9,7073.2 r0 top
R157 "100kΩ" R0402#4 4930.8,6963.2 r0 top
R158 "0Ω" R0402#4 5059.3,6623.2 r0 top
R159 "100kΩ" R0402#1 5063.8,6773.3 r0 top
R160 "10kΩ" R0402#4 5349.6,6923.4 r0 top
R161 "0Ω" R0402#2 5334.6,6743.4 r0 top
R162 "0Ω" R0402#1 5349.2,6848.4 r0 top
R163 "0Ω" R0402#2 5334.6,6653.4 r0 top
R164 "0Ω" R0402#2 5334.6,6593.4 r0 top
R165 "0Ω" R0402#2 5334.6,6533.4 r0 top
R166 "0Ω" R0402#2 5334.6,6473.4 r0 top
R167 "0Ω" R0402#1 4930.7,6898.4 r0 top
R168 "0Ω" R0402#1 5548.8,7078.3 r0 top
R169 "100kΩ" R0402#4 5103.3,6200.1 r0 top
R170 "20kΩ" R0402#1 4933.8,6338.3 r0 top
R171 "91kΩ" R0402#4 5483.3,6589.4 r0 top
R182 "0Ω" R0402#2 10765.5,7047.3 r0 top
R183 "0Ω" R0402#1 10898.8,7363.3 r0 top
R188 "10K" R0603#1 10378.8,5643.3 r0 top
R189 "10K" R0603#1 10130.4,5444.7 r0 top
R190 "10K" R0603#2 10522.8,5376.9 r90 top
RF1 "KH-IPEX3-2020" IPEX-SMD_4P-L1.7-W1.7-LS2.0-L 5218.8,6898.3 r0 top
SW1 "TS24CA" SW-SMD_TS24CA#1 7052.1,4453 r0 top
SW2 "TS24CA" SW-SMD_TS24CA#2 7742,4403 r0 top
SW3 "TS24CA" SW-SMD_TS24CA#3 7052.1,4076.7 r0 top
SW4 "TS-1088R-02026" SW-SMD_L3.9-W3.0-P4.45#1 7742,4026.7 r0 top
SW5 "TS-1088R-02026" SW-SMD_L3.9-W3.0-P4.45#2 7272.2,3814.5 r0 top
U3 "测试焊盘" 焊盘 10818.5,7637.1 r180 bottom
U4 "测试焊盘" 焊盘 10643.5,7638.7 r180 bottom
U5 "SY6280AAAC" TSOT-23-5_L2.9-W1.6-P0.95-LS2.8-BL#1 4965.5,9416.7 r0 top
U6 "LP6252B6F" SOT-23-6_L2.9-W1.6-P0.95-LS2.8-BL 5343.8,9813.3 r0 top
U7 "AXP707" QFN-68_L8.0-W8.0-P0.40-BL-EP5.5 7883.8,9258.3 r0 top
U9 "SY8089A" SOT-23-5_L3.0-W1.7-P0.95-LS2.8-BL#1 9963.8,5438.3 r0 top
U10 "K4E6E304ED-EGCG" FBGA-178_L11.5-W11.0_MT52L256M32D1PF 7679.4,7741.3 r180 top
U11 "KLMBG2JETD-B041" BGA-153_L13.0-W11.5-P0.50-TL_KLM8G1GEME-B041 7368.8,8753.3 r270 top
U12 "SY6280AAAC" TSOT-23-5_L2.9-W1.6-P0.95-LS2.8-BL#2 4692.5,9894.2 r0 top
U13 "LPA4890MSF" MSOP-8_L3.0-W3.0-P0.65-LS5.0-BL 14971.8,6053.3 r0 top
U14 "LPA4890MSF" MSOP-8_L3.0-W3.0-P0.65-LS5.0-BL 13321.8,5400.4 r0 top
U15 "测试焊盘" 焊盘 8752,3714.5 r0 top
U16 "测试焊盘" 焊盘 7793.6,3576.1 r0 top
U27 "测试焊盘" 焊盘 8752,3551.1 r0 top
U30 "测试焊盘" 焊盘 7793.6,3477.6 r0 top
U31 "" QFN-44_L12.0-W12.0-P0.90-AW869A 6368.8,6688.3 r0 top
U32 "SY8088IAAC" SOT-23-5_L3.0-W1.7-P0.95-LS2.8-BL#2 5239.9,6200.1 r0 top
U34 "A133" LFBGA-346_L12.0-W12.0-P0.50-TL_ALLWINNER_A133 6914,7914.7 r90 top
USB1 "TYPE-C 6P(040新)" USB-C-SMD_TYPE-C-6P 8248.8,9953.3 r180 top
USB2 "TYPEC-307DSW-ACP16" USB-C-SMD_XUNPU_TYPEC-304A-ACP16L#1 7143.8,6353.3 r0 top
USB3 "TYPEC-307DSW-ACP16" USB-C-SMD_XUNPU_TYPEC-304A-ACP16L#2 6258.8,9948.3 r180 top
X1 "24MHz" CRYSTAL-SMD_4P-L3.2-W2.5-BL 6922.5,7329.9 r0 top
X2 "32.768kHz" OSC-SMD_L3.2-W1.5 5011.5,8104.1 r0 top

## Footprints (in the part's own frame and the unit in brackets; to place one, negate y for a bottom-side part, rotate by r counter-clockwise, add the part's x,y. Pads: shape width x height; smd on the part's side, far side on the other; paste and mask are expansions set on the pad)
AUDIO-TH_ST-0277D00-052-142 [mil]
  oval 70.9x39.4 hole 23.6 slot 51.2 at 0 deg paste+0 mask+2: 1(-177.2,159.4) 2(-143.7,-159.5) 3(-31.5,159.4)
  oval 78.7x39.4 hole 23.6 slot 59.1 at 0 deg paste+0 mask+2: 4(177.1,-159.5) 5(177.1,159.4)
  Board Outline Layer lines w10: -270,130 244.1,130 244.1,-130 -270,-130
  silkscreen extent -275,-140 255,140
BGA-153_L13.0-W11.5-P0.50-TL_KLM8G1GEME-B041 [mil]
  round 9.6 smd paste-3937 mask+2: A1(-127.9,128) A2(-108.2,128) A3(-88.6,128) A4(-68.9,128) A5(-49.2,128) A6(-29.5,128) A7(-9.8,128) A8(9.9,128) A9(29.6,128) A10(49.2,128) A11(68.9,128) A12(88.6,128) A13(108.3,128) A14(128,128) B1(-127.9,108.3) B2(-108.2,108.3) B3(-88.6,108.3) B4(-68.9,108.3) B5(-49.2,108.3) B6(-29.5,108.3) B7(-9.8,108.3) B8(9.9,108.3) B9(29.6,108.3) B10(49.2,108.3) B11(68.9,108.3) B12(88.6,108.3) B13(108.3,108.3) B14(128,108.3) C1(-127.9,88.6) C2(-108.2,88.6) C3(-88.6,88.6) C4(-68.9,88.6) C5(-49.2,88.6) C6(-29.5,88.6) C7(-9.8,88.6) C8(9.9,88.6) C9(29.6,88.6) C10(49.2,88.6) C11(68.9,88.6) C12(88.6,88.6) C13(108.3,88.6) C14(128,88.6) D1(-127.9,68.9) D2(-108.2,68.9) D3(-88.6,68.9) D4(-68.9,68.9) D12(88.6,68.9) D13(108.3,68.9) D14(128,68.9) E1(-127.9,49.2) E2(-108.2,49.2) E3(-88.6,49.2) E5(-49.2,49.2) E6(-29.5,49.2) E7(-9.8,49.2) E8(9.9,49.2) E9(29.6,49.2) E10(49.2,49.2) E12(88.6,49.2) E13(108.3,49.2) E14(128,49.2) F1(-127.9,29.6) F2(-108.2,29.6) F3(-88.6,29.6) F5(-49.2,29.6) F10(49.2,29.6) F12(88.6,29.6) F13(108.3,29.6) F14(128,29.6) G1(-127.9,9.9) G2(-108.2,9.9) G3(-88.6,9.9) G5(-49.2,9.9) G10(49.2,9.9) G12(88.6,9.9) G13(108.3,9.9) G14(128,9.9) H1(-127.9,-9.8) H2(-108.2,-9.8) H3(-88.6,-9.8) H5(-49.2,-9.8) H10(49.2,-9.8) H12(88.6,-9.8) H13(108.3,-9.8) H14(128,-9.8) J1(-127.9,-29.5) J2(-108.2,-29.5) J3(-88.6,-29.5) J5(-49.2,-29.5) J10(49.2,-29.5) J12(88.6,-29.5) J13(108.3,-29.5) J14(128,-29.5) K1(-127.9,-49.2) K2(-108.2,-49.2) K3(-88.6,-49.2) K5(-49.2,-49.2) K6(-29.5,-49.2) K7(-9.8,-49.2) K8(9.9,-49.2) K9(29.6,-49.2) K10(49.2,-49.2) K12(88.6,-49.2) K13(108.3,-49.2) K14(128,-49.2) L1(-127.9,-68.9) L2(-108.2,-68.9) L3(-88.6,-68.9) L12(88.6,-68.9) L13(108.3,-68.9) L14(128,-68.9) M1(-127.9,-88.5) M2(-108.2,-88.5) M3(-88.6,-88.5) M4(-68.9,-88.5) M5(-49.2,-88.5) M6(-29.5,-88.5) M7(-9.8,-88.5) M8(9.9,-88.5) M9(29.6,-88.5) M10(49.2,-88.5) M11(68.9,-88.5) M12(88.6,-88.5) M13(108.3,-88.5) M14(128,-88.5) N1(-127.9,-108.2) N2(-108.2,-108.2) N3(-88.6,-108.2) N4(-68.9,-108.2) N5(-49.2,-108.2) N6(-29.5,-108.2) N7(-9.8,-108.2) N8(9.9,-108.2) N9(29.6,-108.2) N10(49.2,-108.2) N11(68.9,-108.2) N12(88.6,-108.2) N13(108.3,-108.2) N14(128,-108.2) P1(-127.9,-127.9) P2(-108.2,-127.9) P3(-88.6,-127.9) P4(-68.9,-127.9) P5(-49.2,-127.9) P6(-29.5,-127.9) P7(-9.8,-127.9) P8(9.9,-127.9) P9(29.6,-127.9) P10(49.2,-127.9) P11(68.9,-127.9) P12(88.6,-127.9) P13(108.3,-127.9) P14(128,-127.9)
  silkscreen extent -257,-259 229,268
C0402#1 [mil]
  rect 22.3x21.3 smd paste-3937 mask+2: 1(-17.1,0) 2(17,0)
  silkscreen extent -37,-20 37,20
C0402#2 [mil]
  rect 22.3x21.3 smd paste-3937 mask+2: 1(-17,0) 2(17.1,0)
  silkscreen extent -37,-20 37,20
C0402#3 [mil]
  rect 22.3x21.3 smd paste-3937 mask+2: 1(-17,0) 2(17,0)
  silkscreen extent -37,-20 37,20
C0402#4 [mil]
  rect 22.3x21.3 smd paste-3937 mask+2: 1(-17.04,0.07) 2(17.04,0.07)
  silkscreen extent -37,-20 37,20
C0402#5 [mil]
  rect 22.3x21.3 smd paste-3937 mask+2: 1(-16.97,0) 2(17.04,0.07)
  silkscreen extent -37,-20 37,20
C0603#1 [mil]
  rect 31.5x35.4 smd: 1(-27.6,0) 2(27.6,0)
  silkscreen extent -55,-28 55,28
C0603#2 [mil]
  rect 31.5x35.4 smd: 1(-27.6,0) 2(27.5,0)
  silkscreen extent -55,-28 55,28
C0603#3 [mil]
  rect 31.5x35.4 smd: 1(-27.5,0) 2(27.6,0)
  silkscreen extent -55,-28 55,28
C0603#4 [mil]
  rect 31.5x35.4 smd paste+0 mask+2: 1(-27.6,0) 2(27.6,0)
  silkscreen extent -55,-28 55,28
C0603#5 [mil]
  rect 31.5x35.4 smd paste+0 mask+2: 1(-27.6,0) 2(27.5,0)
  silkscreen extent -55,-28 55,28
CONN-SMD_2P-P1.00_DEALON_1.0-2PWB [mil]
  rect 27.6x70.9 smd paste+0 mask+2: 1(-19.7,76.7) 2(19.7,76.7)
  rect 47.2x78.7 smd paste+0 mask+2: 3(70.9,-76.8) 4(-70.8,-76.8)
  silkscreen extent -79,-108 79,88
CONN-SMD_5P-P1.25_L5.5-W11.4-5PWB [mil]
  rect 31.5x74.8 smd paste+0 mask+2: 1(-100,95.9) 2(-50.8,95.9) 3(-1.5,95.9) 4(50,95.9) 5(100,95.9)
  rect 51.2x131.9 smd paste+0 mask+2: 6(212.2,-96) 7(-212.2,-96)
  silkscreen extent -224,-134 221,115
CRYSTAL-SMD_4P-L3.2-W2.5-BL [mil]
  rect 55.1x47.2 smd paste+0 mask+2: 1(-43.4,-33.4) 2(43.3,-33.4) 3(43.3,33.5) 4(-43.4,33.5)
  silkscreen extent -89,-75 80,66
DFN-6L_L2.0-W2.0-P0.65-BL_CJM1216 [mil]
  rect 14.5x17.5 smd paste+0 mask+2: 1(-28.5,-41) 2(-2.5,-41) 3(23.5,-41) 4(23.5,40.9) 5(-2.5,40.9) 6(-28.5,40.9)
  rect 49.5x43.5 smd paste+0 mask+2: 7(-13.5,0)
  rect 14.5x26.5 smd paste+0 mask+2: 8(28.5,0)
  silkscreen extent -47,-64 39,39
FBGA-178_L11.5-W11.0_MT52L256M32D1PF [mil]
  round 9.8 smd paste+0 mask+2: A1(-188.9,204.7) A2(-157.4,204.7) A3(-125.9,204.7) A4(-94.4,204.7) A5(-62.9,204.7) A6(-31.5,204.7) A8(31.5,204.7) A9(63,204.7) A10(94.5,204.7) A11(126,204.7) A12(157.5,204.7) A13(189,204.7) B1(-188.9,179.1) B2(-157.4,179.1) B3(-125.9,179.1) B4(-94.4,179.1) B5(-62.9,179.1) B6(-31.5,179.1) B8(31.5,179.1) B9(63,179.1) B10(94.5,179.1) B11(126,179.1) B12(157.5,179.1) B13(189,179.1) C2(-157.4,153.6) C3(-125.9,153.6) C4(-94.4,153.6) C5(-62.9,153.6) C6(-31.5,153.6) C8(31.5,153.6) C9(63,153.6) C10(94.5,153.6) C11(126,153.6) C12(157.5,153.6) D2(-157.4,128) D3(-125.9,128) D4(-94.4,128) D5(-62.9,128) D6(-31.5,128) D8(31.5,128) D9(63,128) D10(94.5,128) D11(126,128) D12(157.5,128) E2(-157.4,102.4) E3(-125.9,102.4) E4(-94.4,102.4) E5(-62.9,102.4) E6(-31.5,102.4) E8(31.5,102.4) E9(63,102.4) E10(94.5,102.4) E11(126,102.4) E12(157.5,102.4) F2(-157.4,76.8) F3(-125.9,76.8) F4(-94.4,76.8) F5(-62.9,76.8) F6(-31.5,76.8) F8(31.5,76.8) F9(63,76.8) F10(94.5,76.8) F11(126,76.8) F12(157.5,76.8) G2(-157.4,51.2) G3(-125.9,51.2) G4(-94.4,51.2) G5(-62.9,51.2) G6(-31.5,51.2) G8(31.5,51.2) G9(63,51.2) G10(94.5,51.2) G11(126,51.2) G12(157.5,51.2) H2(-157.4,25.6) H3(-125.9,25.6) H4(-94.4,25.6) H5(-62.9,25.6) H6(-31.5,25.6) H8(31.5,25.6) H9(63,25.6) H10(94.5,25.6) H11(126,25.6) H12(157.5,25.6) J2(-157.4,0) J3(-125.9,0) J4(-94.4,0) J5(-62.9,0) J6(-31.5,0) J8(31.5,0) J9(63,0) J10(94.5,0) J11(126,0) J12(157.5,0) K2(-157.4,-25.6) K3(-125.9,-25.6) K4(-94.4,-25.6) K5(-62.9,-25.6) K6(-31.5,-25.6) K8(31.5,-25.6) K9(63,-25.6) K10(94.5,-25.6) K11(126,-25.6) K12(157.5,-25.6) L2(-157.4,-51.2) L3(-125.9,-51.2) L4(-94.4,-51.2) L5(-62.9,-51.2) L6(-31.5,-51.2) L8(31.5,-51.2) L9(63,-51.2) L10(94.5,-51.2) L11(126,-51.2) L12(157.5,-51.2) M2(-157.4,-76.8) M3(-125.9,-76.8) M4(-94.4,-76.8) M5(-62.9,-76.8) M6(-31.5,-76.8) M8(31.5,-76.8) M9(63,-76.8) M10(94.5,-76.8) M11(126,-76.8) M12(157.5,-76.8) N2(-157.4,-102.3) N3(-125.9,-102.3) N4(-94.4,-102.3) N5(-62.9,-102.3) N6(-31.5,-102.3) N8(31.5,-102.3) N9(63,-102.3) N10(94.5,-102.3) N11(126,-102.3) N12(157.5,-102.3) P2(-157.4,-127.9) P3(-125.9,-127.9) P4(-94.4,-127.9) P5(-62.9,-127.9) P6(-31.5,-127.9) P8(31.5,-127.9) P9(63,-127.9) P10(94.5,-127.9) P11(126,-127.9) P12(157.5,-127.9) R2(-157.4,-153.5) R3(-125.9,-153.5) R4(-94.4,-153.5) R5(-62.9,-153.5) R6(-31.5,-153.5) R8(31.5,-153.5) R9(63,-153.5) R10(94.5,-153.5) R11(126,-153.5) R12(157.5,-153.5) T1(-188.9,-179.1) T2(-157.4,-179.1) T3(-125.9,-179.1) T4(-94.4,-179.1) T5(-62.9,-179.1) T6(-31.5,-179.1) T8(31.5,-179.1) T9(63,-179.1) T10(94.5,-179.1) T11(126,-179.1) T12(157.5,-179.1) T13(189,-179.1) U1(-188.9,-204.7) U2(-157.4,-204.7) U3(-125.9,-204.7) U4(-94.4,-204.7) U5(-62.9,-204.7) U6(-31.5,-204.7) U8(31.5,-204.7) U9(63,-204.7) U10(94.5,-204.7) U11(126,-204.7) U12(157.5,-204.7) U13(189,-204.7)
  silkscreen extent -232,-230 220,240
IND-SMD_L2.5-W2.0_MHCH252012A [mil]
  rect 39.4x86.6 smd paste+0 mask+2: 1(-37.4,0) 2(37.4,0)
  silkscreen extent -49,-49 49,49
IND-SMD_L3.0-W3.0#1 [mil]
  rect 59.1x130.7 smd paste+0 mask+2: 1(52.3,0) 2(-52.3,0)
  silkscreen extent -60,-75 60,75
IND-SMD_L3.0-W3.0#2 [mil]
  rect 59.1x130.7 smd: 1(52.3,0) 2(-52.3,0)
  silkscreen extent -60,-75 60,75
IPEX-SMD_4P-L1.7-W1.7-LS2.0-L [mil]
  rect 39.4x19.7 smd: 1(-39.3,0)
  rect 59.1x23.6 smd: 2(1,-39.4) 4(1,39.3)
  rect 25.6x19.7 smd: 3(39.4,0)
  silkscreen extent -57,-35 41,35
L0603 [mil]
  rect 31.5x34 smd paste-3937 mask+2: 1(-27.5,0) 2(27.6,0)
  silkscreen extent -56,-26 56,26
LED-SMD_L1.7-W1.1-R-RD_GREEN [mil]
  rect 23.6x31.5 smd: 1(29.6,0) 2(-29.5,0)
  silkscreen extent -19,-10 19,33
LFBGA-346_L12.0-W12.0-P0.50-TL_ALLWINNER_A133 [mil]
  oval 9.1x9.6 smd paste+0 mask+2: A1(-216.6,216.5) A7(-98.4,216.5) A12(0,216.5) A13(19.7,216.5) A14(39.3,216.5) A15(59,216.5) A16(78.7,216.5) A17(98.4,216.5) AA13(19.7,-177.2) AA14(39.3,-177.2) AB3(-177.2,-196.9) AB4(-157.5,-196.9) AB5(-137.8,-196.9) AB6(-118.1,-196.9) AB7(-98.4,-196.9) AB8(-78.8,-196.9) AB9(-59.1,-196.9) AB10(-39.4,-196.9) AB11(-19.7,-196.9) AB12(0,-196.9) AB13(19.7,-196.9) AB14(39.3,-196.9) AB15(59,-196.9) AB16(78.7,-196.9) AB17(98.4,-196.9) AB18(118.1,-196.9) AB19(137.8,-196.9) AB20(157.5,-196.9) AC2(-196.9,-216.6) AC9(-59.1,-216.6) AC11(-19.7,-216.6) AC17(98.4,-216.6) AC19(137.8,-216.6) AC21(177.1,-216.6) AC22(196.8,-216.6) B3(-177.2,196.8) B4(-157.5,196.8) B5(-137.8,196.8) B6(-118.1,196.8) B7(-98.4,196.8) B8(-78.8,196.8) B9(-59.1,196.8) B10(-39.4,196.8) B11(-19.7,196.8) B12(0,196.8) B17(98.4,196.8) B18(118.1,196.8) B19(137.8,196.8) B20(157.5,196.8) B21(177.1,196.8)
  round 9.1 smd paste+0 mask+2: A2(-196.9,216.5) AB1(-216.6,-196.9) AB2(-196.9,-196.9) AC1(-216.6,-216.6) B2(-196.9,196.8) L2(-196.9,19.6)
  oval 7.8x9.6 smd paste+0 mask+2: A3(-177.2,216.5) AC7(-98.4,-216.6)
  oval 7.9x9.6 smd paste+0 mask+2: A5(-137.8,216.5) A9(-59.1,216.5) A11(-19.7,216.5) A19(137.8,216.5) A21(177.1,216.5) AC3(-177.2,-216.6) AC5(-137.8,-216.6)
  round 9.6 smd paste+0 mask+2: A22(196.8,216.5) AA3(-177.2,-177.2) AA4(-157.5,-177.2) AA5(-137.8,-177.2) AA6(-118.1,-177.2) AA7(-98.4,-177.2) AA8(-78.8,-177.2) AA9(-59.1,-177.2) AA10(-39.4,-177.2) AA11(-19.7,-177.2) AA12(0,-177.2) AA15(59,-177.2) AA16(78.7,-177.2) AA17(98.4,-177.2) AA18(118.1,-177.2) AA19(137.8,-177.2) AA20(157.5,-177.2) AA21(177.1,-177.2) AA22(196.8,-177.2) AB22(196.8,-196.9) AC13(19.7,-216.6) AC15(59,-216.6) B13(19.7,196.8) B14(39.3,196.8) B15(59,196.8) B16(78.7,196.8) B22(196.8,196.8) C3(-177.2,177.1) C4(-157.5,177.1) C5(-137.8,177.1) C6(-118.1,177.1) C7(-98.4,177.1) C8(-78.8,177.1) C9(-59.1,177.1) C10(-39.4,177.1) C11(-19.7,177.1) C13(19.7,177.1) C15(59,177.1) C17(98.4,177.1) C18(118.1,177.1) C19(137.8,177.1) C20(157.5,177.1) C21(177.1,177.1) D3(-177.2,157.4) D4(-157.5,157.4) D5(-137.8,157.4) D7(-98.4,157.4) D9(-59.1,157.4) D11(-19.7,157.4) D13(19.7,157.4) D15(59,157.4) D17(98.4,157.4) D19(137.8,157.4) D21(177.1,157.4) E3(-177.2,137.7) E5(-137.8,137.7) E7(-98.4,137.7) E9(-59.1,137.7) E11(-19.7,137.7) E13(19.7,137.7) E15(59,137.7) E17(98.4,137.7) E20(157.5,137.7) E21(177.1,137.7) E22(196.8,137.7) F3(-177.2,118.1) F9(-59.1,118.1) F11(-19.7,118.1) F13(19.7,118.1) F22(196.8,118.1) G3(-177.2,98.4) G4(-157.5,98.4) G5(-137.8,98.4) G6(-118.1,98.4) G19(137.8,98.4) G20(157.5,98.4) G21(177.1,98.4) G22(196.8,98.4) H3(-177.2,78.7) H8(-78.8,78.7) H9(-59.1,78.7) H10(-39.4,78.7) H11(-19.7,78.7) H12(0,78.7) H13(19.7,78.7) H14(39.3,78.7) H15(59,78.7) H16(78.7,78.7) J3(-177.2,59) J4(-157.5,59) J5(-137.8,59) J6(-118.1,59) J8(-78.8,59) J9(-59.1,59) J10(-39.4,59) J15(59,59) J16(78.7,59) J18(118.1,59) J19(137.8,59) J20(157.5,59) J21(177.1,59) K3(-177.2,39.3) K8(-78.8,39.3) K9(-59.1,39.3) K10(-39.4,39.3) K11(-19.7,39.3) K12(0,39.3) K13(19.7,39.3) K14(39.3,39.3) K15(59,39.3) K16(78.7,39.3) K21(177.1,39.3) L3(-177.2,19.6) L4(-157.5,19.6) L5(-137.8,19.6) L6(-118.1,19.6) L8(-78.8,19.6) L9(-59.1,19.6) L10(-39.4,19.6) L14(39.3,19.6) L15(59,19.6) L16(78.7,19.6) L18(118.1,19.6) L19(137.8,19.6) L20(157.5,19.6) M3(-177.2,0) M8(-78.8,0) M9(-59.1,0) M10(-39.4,0) M11(-19.7,0) M12(0,0) M13(19.7,0) M14(39.3,0) M15(59,0) M16(78.7,0) N3(-177.2,-19.7) N4(-157.5,-19.7) N5(-137.8,-19.7) N6(-118.1,-19.7) N8(-78.8,-19.7) N9(-59.1,-19.7) N15(59,-19.7) N16(78.7,-19.7) N18(118.1,-19.7) N19(137.8,-19.7) N20(157.5,-19.7) P8(-78.8,-39.4) P9(-59.1,-39.4) P10(-39.4,-39.4) P11(-19.7,-39.4) P12(0,-39.4) P13(19.7,-39.4) P14(39.3,-39.4) P15(59,-39.4) P16(78.7,-39.4) P21(177.1,-39.4) R4(-157.5,-59.1) R5(-137.8,-59.1) R6(-118.1,-59.1) R8(-78.8,-59.1) R9(-59.1,-59.1) R10(-39.4,-59.1) R11(-19.7,-59.1) R12(0,-59.1) R13(19.7,-59.1) R14(39.3,-59.1) R15(59,-59.1) R16(78.7,-59.1) R18(118.1,-59.1) R19(137.8,-59.1) R20(157.5,-59.1) R21(177.1,-59.1) T3(-177.2,-78.8) T21(177.1,-78.8) U1(-216.6,-98.5) U2(-196.9,-98.5) U3(-177.2,-98.5) U4(-157.5,-98.5) U5(-137.8,-98.5) U7(-98.4,-98.5) U9(-59.1,-98.5) U11(-19.7,-98.5) U13(19.7,-98.5) U15(59,-98.5) U17(98.4,-98.5) U18(118.1,-98.5) U19(137.8,-98.5) U20(157.5,-98.5) U21(177.1,-98.5) V3(-177.2,-118.1) V7(-98.4,-118.1) V9(-59.1,-118.1) V11(-19.7,-118.1) V13(19.7,-118.1) V15(59,-118.1) V17(98.4,-118.1) V22(196.8,-118.1) W4(-157.5,-137.8) W7(-98.4,-137.8) W9(-59.1,-137.8) W11(-19.7,-137.8) W13(19.7,-137.8) W15(59,-137.8) W17(98.4,-137.8) W20(157.5,-137.8) W21(177.1,-137.8) W22(196.8,-137.8) Y4(-157.5,-157.5) Y5(-137.8,-157.5) Y7(-98.4,-157.5) Y9(-59.1,-157.5) Y11(-19.7,-157.5) Y13(19.7,-157.5) Y15(59,-157.5) Y17(98.4,-157.5) Y19(137.8,-157.5) Y22(196.8,-157.5)
  oval 9.6x9.1 smd paste+0 mask+2: A23(216.5,216.5) AA1(-216.6,-177.2) AA2(-196.9,-177.2) AA23(216.5,-177.2) AB23(216.5,-196.9) AC23(216.5,-216.6) B1(-216.6,196.8) B23(216.5,196.8) C2(-196.9,177.1) C22(196.8,177.1) C23(216.5,177.1) D2(-196.9,157.4) D22(196.8,157.4) E2(-196.9,137.7) E23(216.5,137.7) F2(-196.9,118.1) F23(216.5,118.1) G2(-196.9,98.4) G23(216.5,98.4) H2(-196.9,78.7) H22(196.8,78.7) H23(216.5,78.7) J2(-196.9,59) J22(196.8,59) J23(216.5,59) K2(-196.9,39.3) K22(196.8,39.3) L21(177.1,19.6) L22(196.8,19.6) L23(216.5,19.6) M2(-196.9,0) M21(177.1,0) M22(196.8,0) N2(-196.9,-19.7) N21(177.1,-19.7) N22(196.8,-19.7) N23(216.5,-19.7) P2(-196.9,-39.4) P3(-177.2,-39.4) P22(196.8,-39.4) R2(-196.9,-59.1) R3(-177.2,-59.1) R22(196.8,-59.1) R23(216.5,-59.1) T2(-196.9,-78.8) T22(196.8,-78.8) U22(196.8,-98.5) U23(216.5,-98.5) V2(-196.9,-118.1) V23(216.5,-118.1) W1(-216.6,-137.8) W2(-196.9,-137.8) W3(-177.2,-137.8) W23(216.5,-137.8) Y2(-196.9,-157.5) Y3(-177.2,-157.5) Y23(216.5,-157.5)
  oval 9.6x7.9 smd paste+0 mask+2: C1(-216.6,177.1) N1(-216.6,-19.7)
  oval 9.6x7.8 smd paste+0 mask+2: E1(-216.6,137.7) G1(-216.6,98.4) J1(-216.6,59) R1(-216.6,-59.1)
  oval 9.1x7.9 smd paste+0 mask+2: L1(-216.6,19.6)
  silkscreen extent -268,-239 239,248
MIC-TH_BD6.0-P1.90-D0.4-L [mil]
  rect 51.2x51.2 hole 27.6 paste+0 mask+2: 1(-37.4,0)
  round 51.2 hole 27.6 paste+0 mask+2: 2(37.4,0)
  silkscreen extent -122,-86 122,157
MSOP-8_L3.0-W3.0-P0.65-LS5.0-BL [mil]
  oval 14.3x66.6 smd paste+0 mask+2: 1(-38.4,-84.5) 2(-12.8,-84.5) 3(12.8,-84.5) 4(38.4,-84.5) 5(38.4,84.5) 6(12.8,84.5) 7(-12.8,84.5) 8(-38.4,84.5)
  silkscreen extent -69,-90 65,68
OSC-SMD_L3.2-W1.5 [mil]
  rect 41.3x66.9 smd paste+0 mask+2: 1(-50.2,0) 2(50.2,0)
  silkscreen extent -80,-42 80,42
QFN-44_L12.0-W12.0-P0.90-AW869A [mil]
  oval 19.7x51.2 smd: 1(-177.1,-238.2) 2(-141.7,-238.2) 3(-106.3,-238.2) 4(-70.8,-238.2) 5(-35.4,-238.2) 6(0,-238.2) 7(35.5,-238.2) 8(70.9,-238.2) 9(106.3,-238.2) 10(141.8,-238.2) 11(177.2,-238.2) 23(177.2,238.2) 24(141.8,238.2) 25(106.3,238.2) 26(70.9,238.2) 27(35.5,238.2) 28(0,238.2) 29(-35.4,238.2) 30(-70.8,238.2) 31(-106.3,238.2) 32(-141.7,238.2) 33(-177.1,238.2)
  oval 51.2x19.7 smd: 12(238.2,-177.2) 13(238.2,-141.8) 14(238.2,-106.3) 15(238.2,-70.9) 16(238.2,-35.5) 17(238.2,0) 18(238.2,35.4) 19(238.2,70.8) 20(238.2,106.3) 21(238.2,141.7) 22(238.2,177.1) 34(-238.2,177.1) 35(-238.2,141.7) 36(-238.2,106.3) 37(-238.2,70.8) 38(-238.2,35.4) 39(-238.2,0) 40(-238.2,-35.5) 41(-238.2,-70.9) 42(-238.2,-106.3) 43(-238.2,-141.8) 44(-238.2,-177.2)
  silkscreen extent -236,-258 236,236
QFN-68_L8.0-W8.0-P0.40-BL-EP5.5 [mil]
  rect 7.9x35.4 smd paste-3937 mask+2: 1(-126,-155.5) 2(-110.2,-155.5) 3(-94.5,-155.5) 4(-78.8,-155.5) 5(-63,-155.5) 6(-47.3,-155.5) 7(-31.5,-155.5) 8(-15.8,-155.5) 9(0,-155.5) 10(15.7,-155.5) 11(31.5,-155.5) 12(47.2,-155.5) 13(63,-155.5) 14(78.7,-155.5) 15(94.5,-155.5) 16(110.2,-155.5) 17(126,-155.5) 35(126,155.5) 36(110.2,155.5) 37(94.5,155.5) 38(78.7,155.5) 39(63,155.5) 40(47.2,155.5) 41(31.5,155.5) 42(15.7,155.5) 43(0,155.5) 44(-15.8,155.5) 45(-31.5,155.5) 46(-47.3,155.5) 47(-63,155.5) 48(-78.8,155.5) 49(-94.5,155.5) 50(-110.2,155.5) 51(-126,155.5)
  rect 35.4x7.9 smd paste-3937 mask+2: 18(155.5,-126) 19(155.5,-110.3) 20(155.5,-94.5) 21(155.5,-78.8) 22(155.5,-63) 23(155.5,-47.3) 24(155.5,-31.5) 25(155.5,-15.8) 26(155.5,0) 27(155.5,15.7) 28(155.5,31.5) 29(155.5,47.2) 30(155.5,63) 31(155.5,78.7) 32(155.5,94.5) 33(155.5,110.2) 34(155.5,126) 52(-155.5,126) 53(-155.5,110.2) 54(-155.5,94.5) 55(-155.5,78.7) 56(-155.5,63) 57(-155.5,47.2) 58(-155.5,31.5) 59(-155.5,15.7) 60(-155.5,0) 61(-155.5,-15.8) 62(-155.5,-31.5) 63(-155.5,-47.3) 64(-155.5,-63) 65(-155.5,-78.8) 66(-155.5,-94.5) 67(-155.5,-110.3) 68(-155.5,-126)
  rect 216.5x216.5 smd paste-3937 mask+2: 69(0,0)
  silkscreen extent -165,-192 165,165
R0402#1 [mil]
  rect 22.3x21.3 smd paste-3937 mask+2: 1(-17,0) 2(17.1,0)
  silkscreen extent -37,-20 37,20
R0402#2 [mil]
  rect 22.3x21.3 smd paste-3937 mask+2: 1(-17,0) 2(17,0)
  silkscreen extent -37,-20 37,20
R0402#3 [mil]
  rect 22.3x21.3 smd paste-3937 mask+2: 1(-17.04,0.07) 2(17.04,0.07)
  silkscreen extent -37,-20 37,20
R0402#4 [mil]
  rect 22.3x21.3 smd paste-3937 mask+2: 1(-17.11,0) 2(16.97,0)
  silkscreen extent -37,-20 37,20
R0603#1 [mil]
  rect 31.8x34 smd paste-3937 mask+2: 1(-29.6,0) 2(29.7,0)
  silkscreen extent -54,-26 55,26
R0603#2 [mil]
  rect 31.8x34 smd paste-3937 mask+2: 1(-29.7,0) 2(29.6,0)
  silkscreen extent -55,-26 54,26
R0805#1 [mil]
  rect 44.6x54.2 smd paste-3937 mask+2: 1(-39.4,0) 2(39.4,0)
  silkscreen extent -69,-36 69,36
R0805#2 [mil]
  rect 44.6x54.2 smd paste-3937 mask+2: 1(-39.3,0) 2(39.4,0)
  silkscreen extent -69,-36 69,36
SOD-923_L0.8-W0.6-LS1.0-BI-1#1 [mil]
  rect 15.7x15.7 smd paste+0 mask+2: 1(-19.7,0) 2(19.7,0)
  silkscreen extent -16,-15 16,15
SOD-923_L0.8-W0.6-LS1.0-BI-1#2 [mil]
  rect 15.7x15.7 smd paste+0 mask+2: 1(-19.7,0) 2(19.6,0)
  silkscreen extent -16,-15 16,15
SOD-923_L0.8-W0.6-LS1.0-BI-1#3 [mil]
  rect 15.7x15.7 smd paste+0 mask+2: 1(-19.6,0) 2(19.7,0)
  silkscreen extent -16,-15 16,15
SOT-23-5_L3.0-W1.7-P0.95-LS2.8-BL#1 [mil]
  rect 19.3x45.6 smd: 1(-37.4,-45.4) 2(0,-45.4) 3(37.4,-45.4)
  rect 19.3x46.3 smd: 4(37.4,45.4) 5(-37.4,45.4)
  silkscreen extent -71,-51 60,34
SOT-23-5_L3.0-W1.7-P0.95-LS2.8-BL#2 [mil]
  rect 19.3x45.6 smd paste+0 mask+2: 1(-37.4,-45.5) 2(0,-45.5) 3(37.4,-45.5)
  rect 19.3x46.3 smd paste+0 mask+2: 4(37.4,45.4) 5(-37.4,45.4)
  silkscreen extent -71,-51 60,34
SOT-23-6_L2.9-W1.6-P0.95-LS2.8-BL [mil]
  rect 20.9x42.2 smd paste+0 mask+2: 1(-37.4,-45.3) 2(0,-45.3) 3(37.4,-45.3) 4(37.4,45.2) 5(0,45.2) 6(-37.4,45.2)
  silkscreen extent -72,-57 61,35
SW-SMD_L3.9-W3.0-P4.45#1 [mil]
  rect 48.4x53.5 smd paste+0 mask+2: 1(-86.1,0) 2(86,0)
  silkscreen extent -80,-64 89,64
SW-SMD_L3.9-W3.0-P4.45#2 [mil]
  rect 48.4x53.5 smd paste+0 mask+2: 1(-86,0) 2(86,0)
  silkscreen extent -80,-64 89,64
SW-SMD_TS24CA#1 [mil]
  rect 35.4x47.2 smd: 1(-90.5,30.5) 2(90.6,30.5)
  rect 47.2x51.2 smd: 3(-65.9,-30.5) 4(66,-30.5)
  Board Outline Layer lines w0.1: -47.1,28.9 -46.4,25.8 -45,22.9 -42.9,20.5 -40.3,18.6 -37.4,17.3 -34.3,16.7 -31.1,16.9 -28,17.8 -25.2,19.4 -22.9,21.6 -21.1,24.3 -20,27.3 -19.7,30.5 -20,33.7 -21.1,36.7 -22.9,39.4 -25.2,41.6 -28,43.2 -31.1,44.1 -34.3,44.3 -37.4,43.7 -40.3,42.4 -42.9,40.5 -45,38.1 -46.4,35.2 -47.1,32.1 -47.1,28.9 ; 19.8,28.9 20.5,25.8 22,22.9 24,20.5 26.6,18.6 29.5,17.3 32.7,16.7 35.9,16.9 38.9,17.8 41.7,19.4 44,21.6 45.8,24.3 46.9,27.3 47.3,30.5 46.9,33.7 45.8,36.7 44,39.4 41.7,41.6 38.9,43.2 35.9,44.1 32.7,44.3 29.5,43.7 26.6,42.4 24,40.5 22,38.1 20.5,35.2 19.8,32.1 19.8,28.9
  Board Outline Layer region: -19.7,30.5 -20,27.3 -21.1,24.3 -22.9,21.6 -25.2,19.4 -28,17.8 -31.1,16.9 -34.3,16.7 -37.4,17.3 -40.3,18.6 -42.9,20.5 -45,22.9 -46.4,25.8 -47.1,28.9 -47.1,32.1 -46.4,35.2 -45,38.1 -42.9,40.5 -40.3,42.4 -37.4,43.7 -34.3,44.3 -31.1,44.1 -28,43.2 -25.2,41.6 -22.9,39.4 -21.1,36.7 -20,33.7
  Board Outline Layer region: -19.7,30.5 -20,27.3 -21.1,24.3 -22.9,21.6 -25.2,19.4 -28,17.8 -31.1,16.9 -34.3,16.7 -37.4,17.3 -40.3,18.6 -42.9,20.5 -45,22.9 -46.4,25.8 -47.1,28.9 -47.1,32.1 -46.4,35.2 -45,38.1 -42.9,40.5 -40.3,42.4 -37.4,43.7 -34.3,44.3 -31.1,44.1 -28,43.2 -25.2,41.6 -22.9,39.4 -21.1,36.7 -20,33.7
  Board Outline Layer region: 47.3,30.5 46.9,27.3 45.8,24.3 44,21.6 41.7,19.4 38.9,17.8 35.9,16.9 32.7,16.7 29.5,17.3 26.6,18.6 24,20.5 22,22.9 20.5,25.8 19.8,28.9 19.8,32.1 20.5,35.2 22,38.1 24,40.5 26.6,42.4 29.5,43.7 32.7,44.3 35.9,44.1 38.9,43.2 41.7,41.6 44,39.4 45.8,36.7 46.9,33.7
  Board Outline Layer region: 47.3,30.5 46.9,27.3 45.8,24.3 44,21.6 41.7,19.4 38.9,17.8 35.9,16.9 32.7,16.7 29.5,17.3 26.6,18.6 24,20.5 22,22.9 20.5,25.8 19.8,28.9 19.8,32.1 20.5,35.2 22,38.1 24,40.5 26.6,42.4 29.5,43.7 32.7,44.3 35.9,44.1 38.9,43.2 41.7,41.6 44,39.4 45.8,36.7 46.9,33.7
  Multi-Layer board cut-out: -19.7,30.5 -20,27.3 -21.1,24.3 -22.9,21.6 -25.2,19.4 -28,17.8 -31.1,16.9 -34.3,16.7 -37.4,17.3 -40.3,18.6 -42.9,20.5 -45,22.9 -46.4,25.8 -47.1,28.9 -47.1,32.1 -46.4,35.2 -45,38.1 -42.9,40.5 -40.3,42.4 -37.4,43.7 -34.3,44.3 -31.1,44.1 -28,43.2 -25.2,41.6 -22.9,39.4 -21.1,36.7 -20,33.7
  Multi-Layer board cut-out: 47.3,30.5 46.9,27.3 45.8,24.3 44,21.6 41.7,19.4 38.9,17.8 35.9,16.9 32.7,16.7 29.5,17.3 26.6,18.6 24,20.5 22,22.9 20.5,25.8 19.8,28.9 19.8,32.1 20.5,35.2 22,38.1 24,40.5 26.6,42.4 29.5,43.7 32.7,44.3 35.9,44.1 38.9,43.2 41.7,41.6 44,39.4 45.8,36.7 46.9,33.7
  silkscreen extent -90,-25 91,113
SW-SMD_TS24CA#2 [mil]
  rect 35.4x47.2 smd: 1(-90.6,30.5) 2(90.5,30.5)
  rect 47.2x51.2 smd: 3(-66,-30.5) 4(65.9,-30.5)
  Board Outline Layer lines w0.1: -47.2,28.9 -46.4,25.8 -45,22.9 -43,20.5 -40.4,18.6 -37.4,17.3 -34.3,16.7 -31.1,16.9 -28,17.8 -25.3,19.4 -22.9,21.6 -21.2,24.3 -20.1,27.3 -19.7,30.5 -20.1,33.7 -21.2,36.7 -22.9,39.4 -25.3,41.6 -28,43.2 -31.1,44.1 -34.3,44.3 -37.4,43.7 -40.4,42.4 -43,40.5 -45,38.1 -46.4,35.2 -47.2,32.1 -47.2,28.9 ; 19.7,28.9 20.5,25.8 21.9,22.9 24,20.5 26.5,18.6 29.5,17.3 32.6,16.7 35.8,16.9 38.9,17.8 41.7,19.4 44,21.6 45.7,24.3 46.8,27.3 47.2,30.5 46.8,33.7 45.7,36.7 44,39.4 41.7,41.6 38.9,43.2 35.8,44.1 32.6,44.3 29.5,43.7 26.5,42.4 24,40.5 21.9,38.1 20.5,35.2 19.7,32.1 19.7,28.9
  Board Outline Layer region: -19.7,30.5 -20.1,27.3 -21.2,24.3 -22.9,21.6 -25.3,19.4 -28,17.8 -31.1,16.9 -34.3,16.7 -37.4,17.3 -40.4,18.6 -43,20.5 -45,22.9 -46.4,25.8 -47.2,28.9 -47.2,32.1 -46.4,35.2 -45,38.1 -43,40.5 -40.4,42.4 -37.4,43.7 -34.3,44.3 -31.1,44.1 -28,43.2 -25.3,41.6 -22.9,39.4 -21.2,36.7 -20.1,33.7
  Board Outline Layer region: -19.7,30.5 -20.1,27.3 -21.2,24.3 -22.9,21.6 -25.3,19.4 -28,17.8 -31.1,16.9 -34.3,16.7 -37.4,17.3 -40.4,18.6 -43,20.5 -45,22.9 -46.4,25.8 -47.2,28.9 -47.2,32.1 -46.4,35.2 -45,38.1 -43,40.5 -40.4,42.4 -37.4,43.7 -34.3,44.3 -31.1,44.1 -28,43.2 -25.3,41.6 -22.9,39.4 -21.2,36.7 -20.1,33.7
  Board Outline Layer region: 47.2,30.5 46.8,27.3 45.7,24.3 44,21.6 41.7,19.4 38.9,17.8 35.8,16.9 32.6,16.7 29.5,17.3 26.5,18.6 24,20.5 21.9,22.9 20.5,25.8 19.7,28.9 19.7,32.1 20.5,35.2 21.9,38.1 24,40.5 26.5,42.4 29.5,43.7 32.6,44.3 35.8,44.1 38.9,43.2 41.7,41.6 44,39.4 45.7,36.7 46.8,33.7
  Board Outline Layer region: 47.2,30.5 46.8,27.3 45.7,24.3 44,21.6 41.7,19.4 38.9,17.8 35.8,16.9 32.6,16.7 29.5,17.3 26.5,18.6 24,20.5 21.9,22.9 20.5,25.8 19.7,28.9 19.7,32.1 20.5,35.2 21.9,38.1 24,40.5 26.5,42.4 29.5,43.7 32.6,44.3 35.8,44.1 38.9,43.2 41.7,41.6 44,39.4 45.7,36.7 46.8,33.7
  Multi-Layer board cut-out: -19.7,30.5 -20.1,27.3 -21.2,24.3 -22.9,21.6 -25.3,19.4 -28,17.8 -31.1,16.9 -34.3,16.7 -37.4,17.3 -40.4,18.6 -43,20.5 -45,22.9 -46.4,25.8 -47.2,28.9 -47.2,32.1 -46.4,35.2 -45,38.1 -43,40.5 -40.4,42.4 -37.4,43.7 -34.3,44.3 -31.1,44.1 -28,43.2 -25.3,41.6 -22.9,39.4 -21.2,36.7 -20.1,33.7
  Multi-Layer board cut-out: 47.2,30.5 46.8,27.3 45.7,24.3 44,21.6 41.7,19.4 38.9,17.8 35.8,16.9 32.6,16.7 29.5,17.3 26.5,18.6 24,20.5 21.9,22.9 20.5,25.8 19.7,28.9 19.7,32.1 20.5,35.2 21.9,38.1 24,40.5 26.5,42.4 29.5,43.7 32.6,44.3 35.8,44.1 38.9,43.2 41.7,41.6 44,39.4 45.7,36.7 46.8,33.7
  silkscreen extent -91,-25 90,113
SW-SMD_TS24CA#3 [mil]
  rect 35.4x47.2 smd: 1(-90.5,30.5) 2(90.6,30.5)
  rect 47.2x51.2 smd: 3(-65.9,-30.6) 4(66,-30.6)
  Board Outline Layer lines w0.1: -47.1,28.9 -46.4,25.8 -45,22.9 -42.9,20.4 -40.3,18.5 -37.4,17.3 -34.3,16.7 -31.1,16.9 -28,17.8 -25.2,19.4 -22.9,21.6 -21.1,24.3 -20,27.3 -19.7,30.5 -20,33.6 -21.1,36.7 -22.9,39.3 -25.2,41.5 -28,43.1 -31.1,44 -34.3,44.2 -37.4,43.7 -40.3,42.4 -42.9,40.5 -45,38 -46.4,35.2 -47.1,32.1 -47.1,28.9 ; 19.8,28.9 20.5,25.8 22,22.9 24,20.4 26.6,18.5 29.5,17.3 32.7,16.7 35.9,16.9 38.9,17.8 41.7,19.4 44,21.6 45.8,24.3 46.9,27.3 47.3,30.5 46.9,33.6 45.8,36.7 44,39.3 41.7,41.5 38.9,43.1 35.9,44 32.7,44.2 29.5,43.7 26.6,42.4 24,40.5 22,38 20.5,35.2 19.8,32.1 19.8,28.9
  Board Outline Layer region: -19.7,30.5 -20,27.3 -21.1,24.3 -22.9,21.6 -25.2,19.4 -28,17.8 -31.1,16.9 -34.3,16.7 -37.4,17.3 -40.3,18.5 -42.9,20.4 -45,22.9 -46.4,25.8 -47.1,28.9 -47.1,32.1 -46.4,35.2 -45,38 -42.9,40.5 -40.3,42.4 -37.4,43.7 -34.3,44.2 -31.1,44 -28,43.1 -25.2,41.5 -22.9,39.3 -21.1,36.7 -20,33.6
  Board Outline Layer region: -19.7,30.5 -20,27.3 -21.1,24.3 -22.9,21.6 -25.2,19.4 -28,17.8 -31.1,16.9 -34.3,16.7 -37.4,17.3 -40.3,18.5 -42.9,20.4 -45,22.9 -46.4,25.8 -47.1,28.9 -47.1,32.1 -46.4,35.2 -45,38 -42.9,40.5 -40.3,42.4 -37.4,43.7 -34.3,44.2 -31.1,44 -28,43.1 -25.2,41.5 -22.9,39.3 -21.1,36.7 -20,33.6
  Board Outline Layer region: 47.3,30.5 46.9,27.3 45.8,24.3 44,21.6 41.7,19.4 38.9,17.8 35.9,16.9 32.7,16.7 29.5,17.3 26.6,18.5 24,20.4 22,22.9 20.5,25.8 19.8,28.9 19.8,32.1 20.5,35.2 22,38 24,40.5 26.6,42.4 29.5,43.7 32.7,44.2 35.9,44 38.9,43.1 41.7,41.5 44,39.3 45.8,36.7 46.9,33.6
  Board Outline Layer region: 47.3,30.5 46.9,27.3 45.8,24.3 44,21.6 41.7,19.4 38.9,17.8 35.9,16.9 32.7,16.7 29.5,17.3 26.6,18.5 24,20.4 22,22.9 20.5,25.8 19.8,28.9 19.8,32.1 20.5,35.2 22,38 24,40.5 26.6,42.4 29.5,43.7 32.7,44.2 35.9,44 38.9,43.1 41.7,41.5 44,39.3 45.8,36.7 46.9,33.6
  Multi-Layer board cut-out: -19.7,30.5 -20,27.3 -21.1,24.3 -22.9,21.6 -25.2,19.4 -28,17.8 -31.1,16.9 -34.3,16.7 -37.4,17.3 -40.3,18.5 -42.9,20.4 -45,22.9 -46.4,25.8 -47.1,28.9 -47.1,32.1 -46.4,35.2 -45,38 -42.9,40.5 -40.3,42.4 -37.4,43.7 -34.3,44.2 -31.1,44 -28,43.1 -25.2,41.5 -22.9,39.3 -21.1,36.7 -20,33.6
  Multi-Layer board cut-out: 47.3,30.5 46.9,27.3 45.8,24.3 44,21.6 41.7,19.4 38.9,17.8 35.9,16.9 32.7,16.7 29.5,17.3 26.6,18.5 24,20.4 22,22.9 20.5,25.8 19.8,28.9 19.8,32.1 20.5,35.2 22,38 24,40.5 26.6,42.4 29.5,43.7 32.7,44.2 35.9,44 38.9,43.1 41.7,41.5 44,39.3 45.8,36.7 46.9,33.6
  silkscreen extent -90,-25 91,113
